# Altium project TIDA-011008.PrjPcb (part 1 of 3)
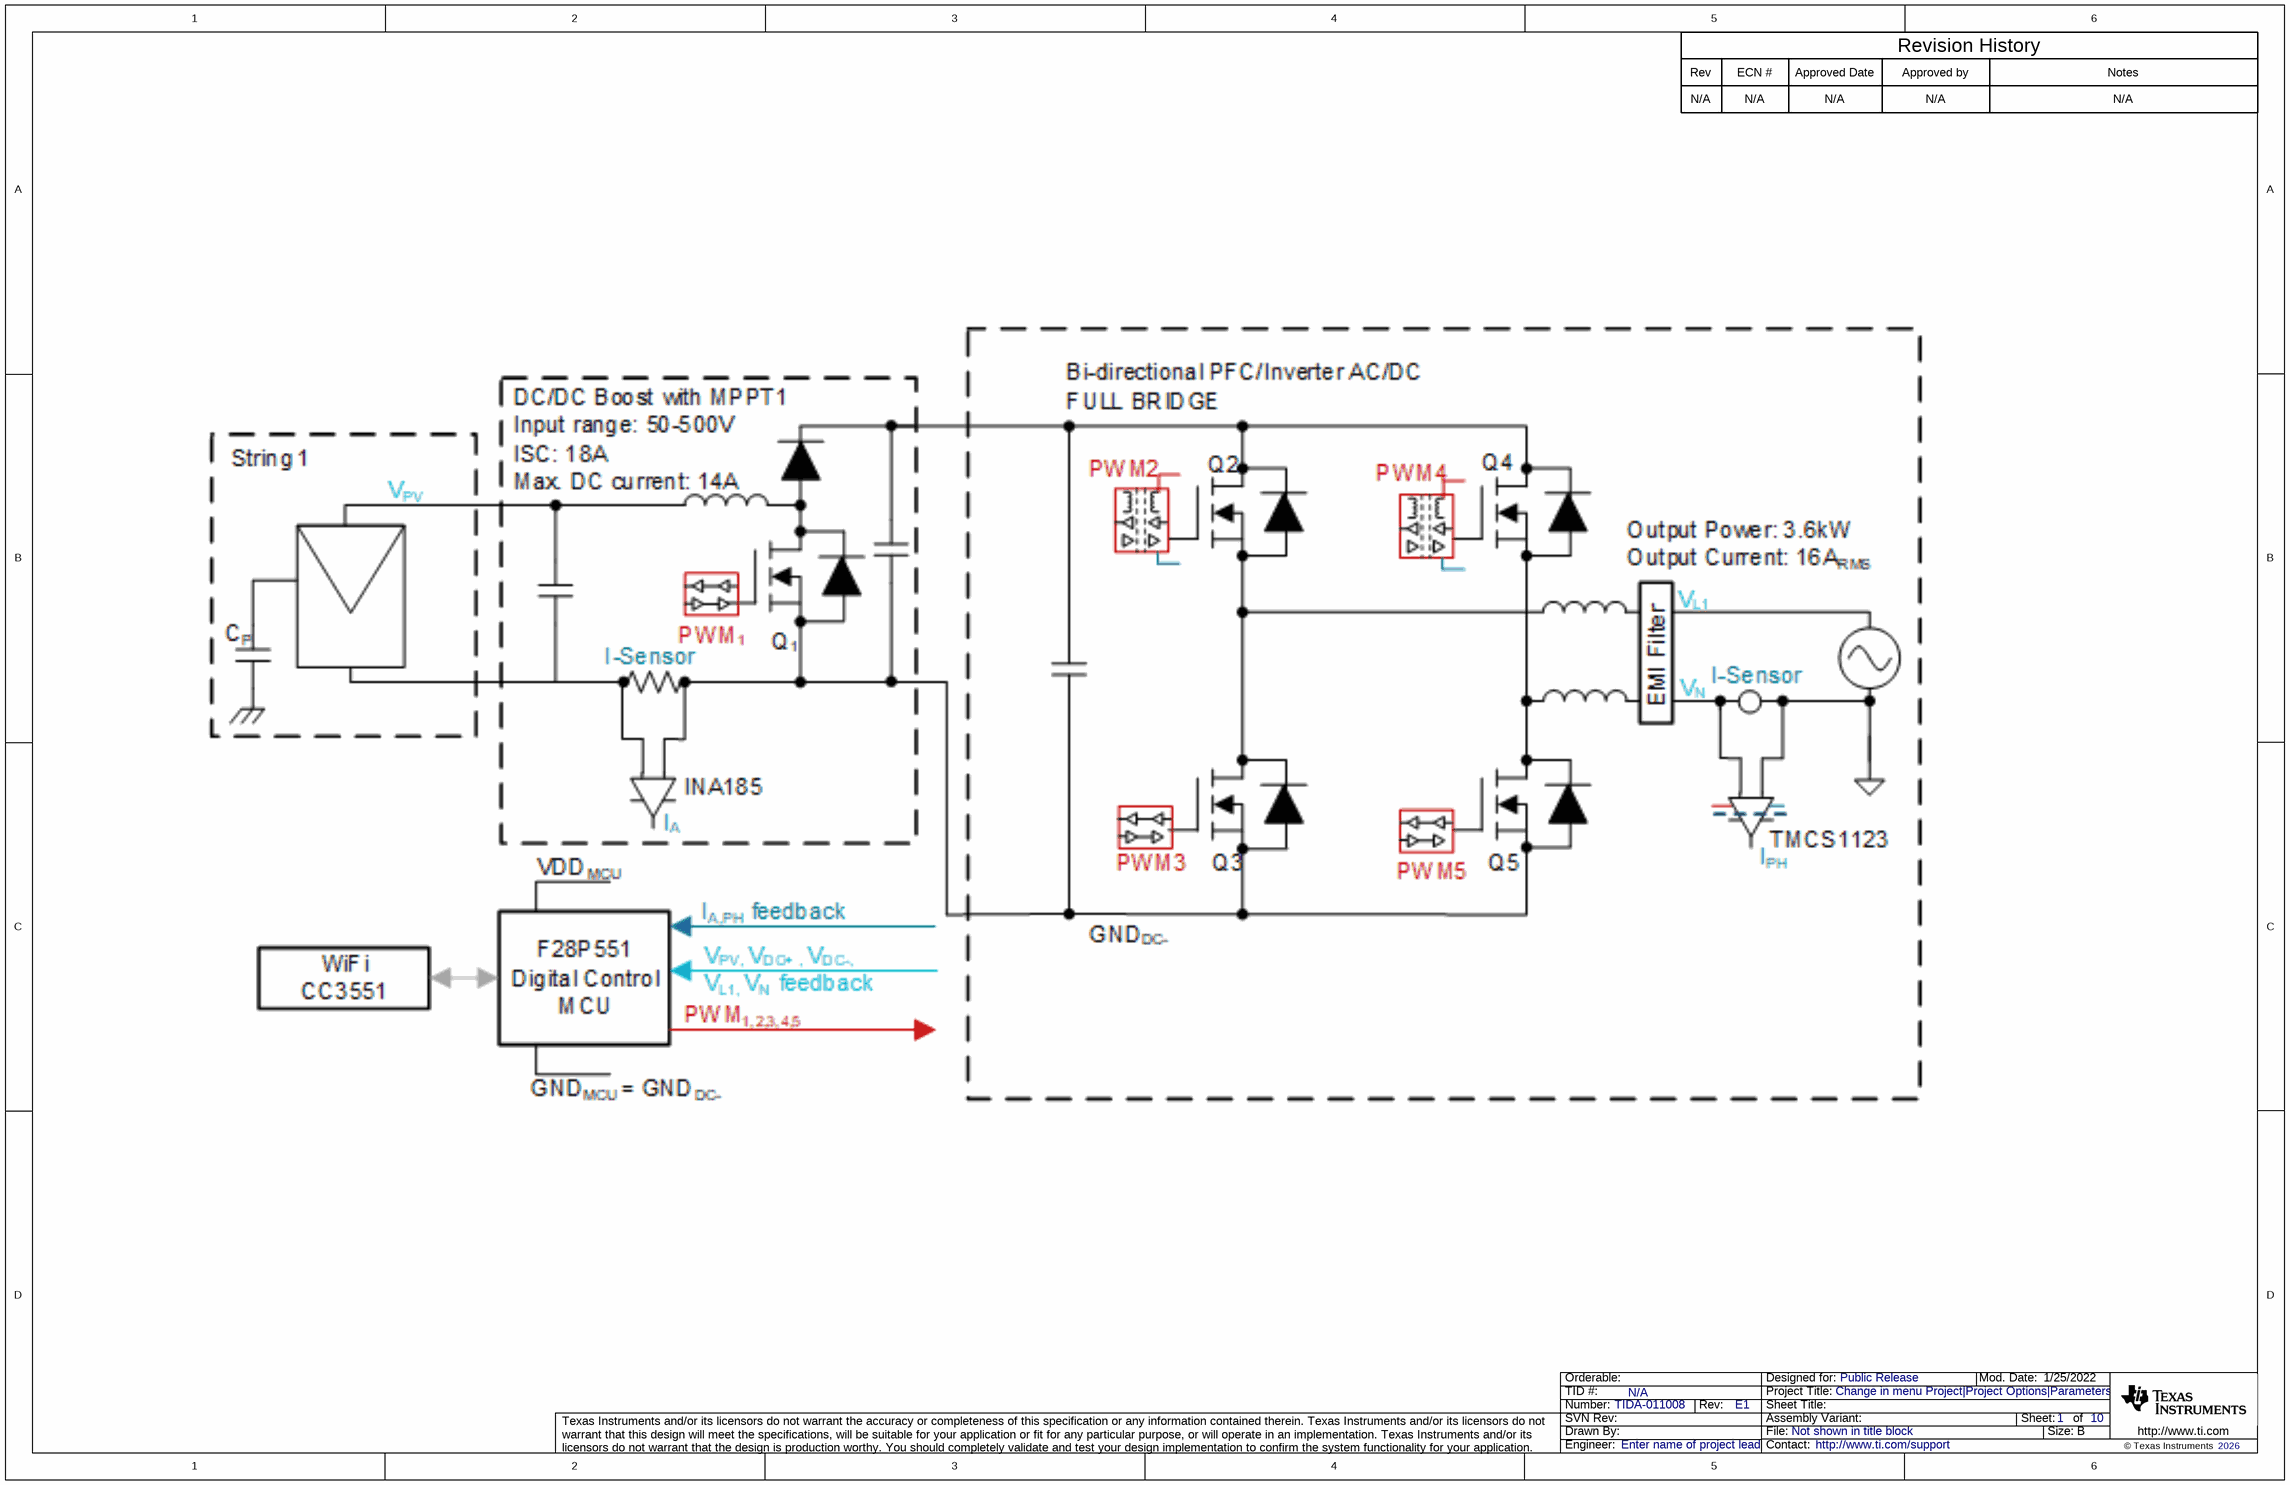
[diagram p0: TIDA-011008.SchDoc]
CopyrightYear: 2026; PCB_Layout: Who did the Layout?; PCB_Rev: E1; PRJ_Customer: Public Release; PRJ_Engineer: Enter name of project lead; PRJ_Number: TIDA-011008; PRJ_Title: Change in menu Project|Project Options|Parameters; SCH_Rev: E1; TechSupport: http://www.ti.com/support; TID: N/A
10 sheets, 518 parts. Net scope: hierarchical (ports join the sheet entries above them; power ports are global).
Board file: TIDA-011008.PcbDoc
Sheets:
  TIDA-011008.SchDoc
  TIDA-011008_CoverSheet.SchDoc
    U_TIDA-011008_Boost = TIDA-011008_Boost.SchDoc
    U_TIDA-011008_ACDC_EMI Filter = TIDA-011008_ACDC_EMI Filter.SchDoc
    U_TIDA-011008_Aux Power = TIDA-011008_Aux Power.SchDoc
    U_TIDA-011008_Control Stage = TIDA-011008_Control Stage.SchDoc
      U_TIDA-011008_WiFi Module = TIDA-011008_WiFi Module.SchDoc
    U_TIDA-011008_ACDC_Leg1 = TIDA-011008_ACDC_Leg.SchDoc
    U_TIDA-011008_ACDC_Leg2 = TIDA-011008_ACDC_Leg.SchDoc
    U_TIDA-011008_Measurements & AD Buffer = TIDA-011008_Measurements & AD Buffer.SchDoc
    U_TIDA-011008_Hardware = TIDA-011008_Hardware.SchDoc

## Sheet TIDA-011008.SchDoc
size 431 x 279 mm; Date: Not shown in title block; ApprovedBy: Not shown in title block; CheckedBy: Not shown in title block; Author: Not shown in title block; CompanyName: Not shown in title block; Engineer: Not shown in title block; Organization: Not shown in title block; Address1: Not shown in title block; Address2: Not shown in title block; Address3: Not shown in title block; Address4: Not shown in title block; DocumentNumber: 1; Revision: Use project parameter SCH_Rev; SheetNumber: 1; SheetTotal: 10; PageSetup: Record=PageOptions¦CenterHorizontal=True¦CenterVertical=True¦PrintScale=1.00¦XCorrection=1.00¦YCorrection=1.00¦PrintKind=0¦BorderSize=5000000¦LeftOffset=0¦BottomOffset=0¦Orientation=2¦PaperLength=1000¦PaperWidth=1000¦Scale=100¦PaperSource=15¦PrintQuality=600¦MediaType=1¦DitherType=10¦PaperKind=Letter¦PrintScaleMode=1

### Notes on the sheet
- Rev
- N/A
- ECN #
- Approved Date
- Approved by
- Revision History
- Notes

## Sheet TIDA-011008_CoverSheet.SchDoc
size 431 x 279 mm; Date: Not shown in title block; ApprovedBy: Not shown in title block; CheckedBy: Not shown in title block; Author: Not shown in title block; CompanyName: Not shown in title block; Engineer: Not shown in title block; Organization: Not shown in title block; Address1: Not shown in title block; Address2: Not shown in title block; Address3: Not shown in title block; Address4: Not shown in title block; DocumentNumber: 2; Revision: Use project parameter SCH_Rev; SheetNumber: 2; SheetTotal: 10; PageSetup: Record=PageOptions¦CenterHorizontal=True¦CenterVertical=True¦PrintScale=1.00¦XCorrection=1.00¦YCorrection=1.00¦PrintKind=0¦BorderSize=5000000¦LeftOffset=0¦BottomOffset=0¦Orientation=2¦PaperLength=1000¦PaperWidth=1000¦Scale=100¦PaperSource=15¦PrintQuality=600¦MediaType=1¦DitherType=10¦PaperKind=Letter¦PrintScaleMode=1
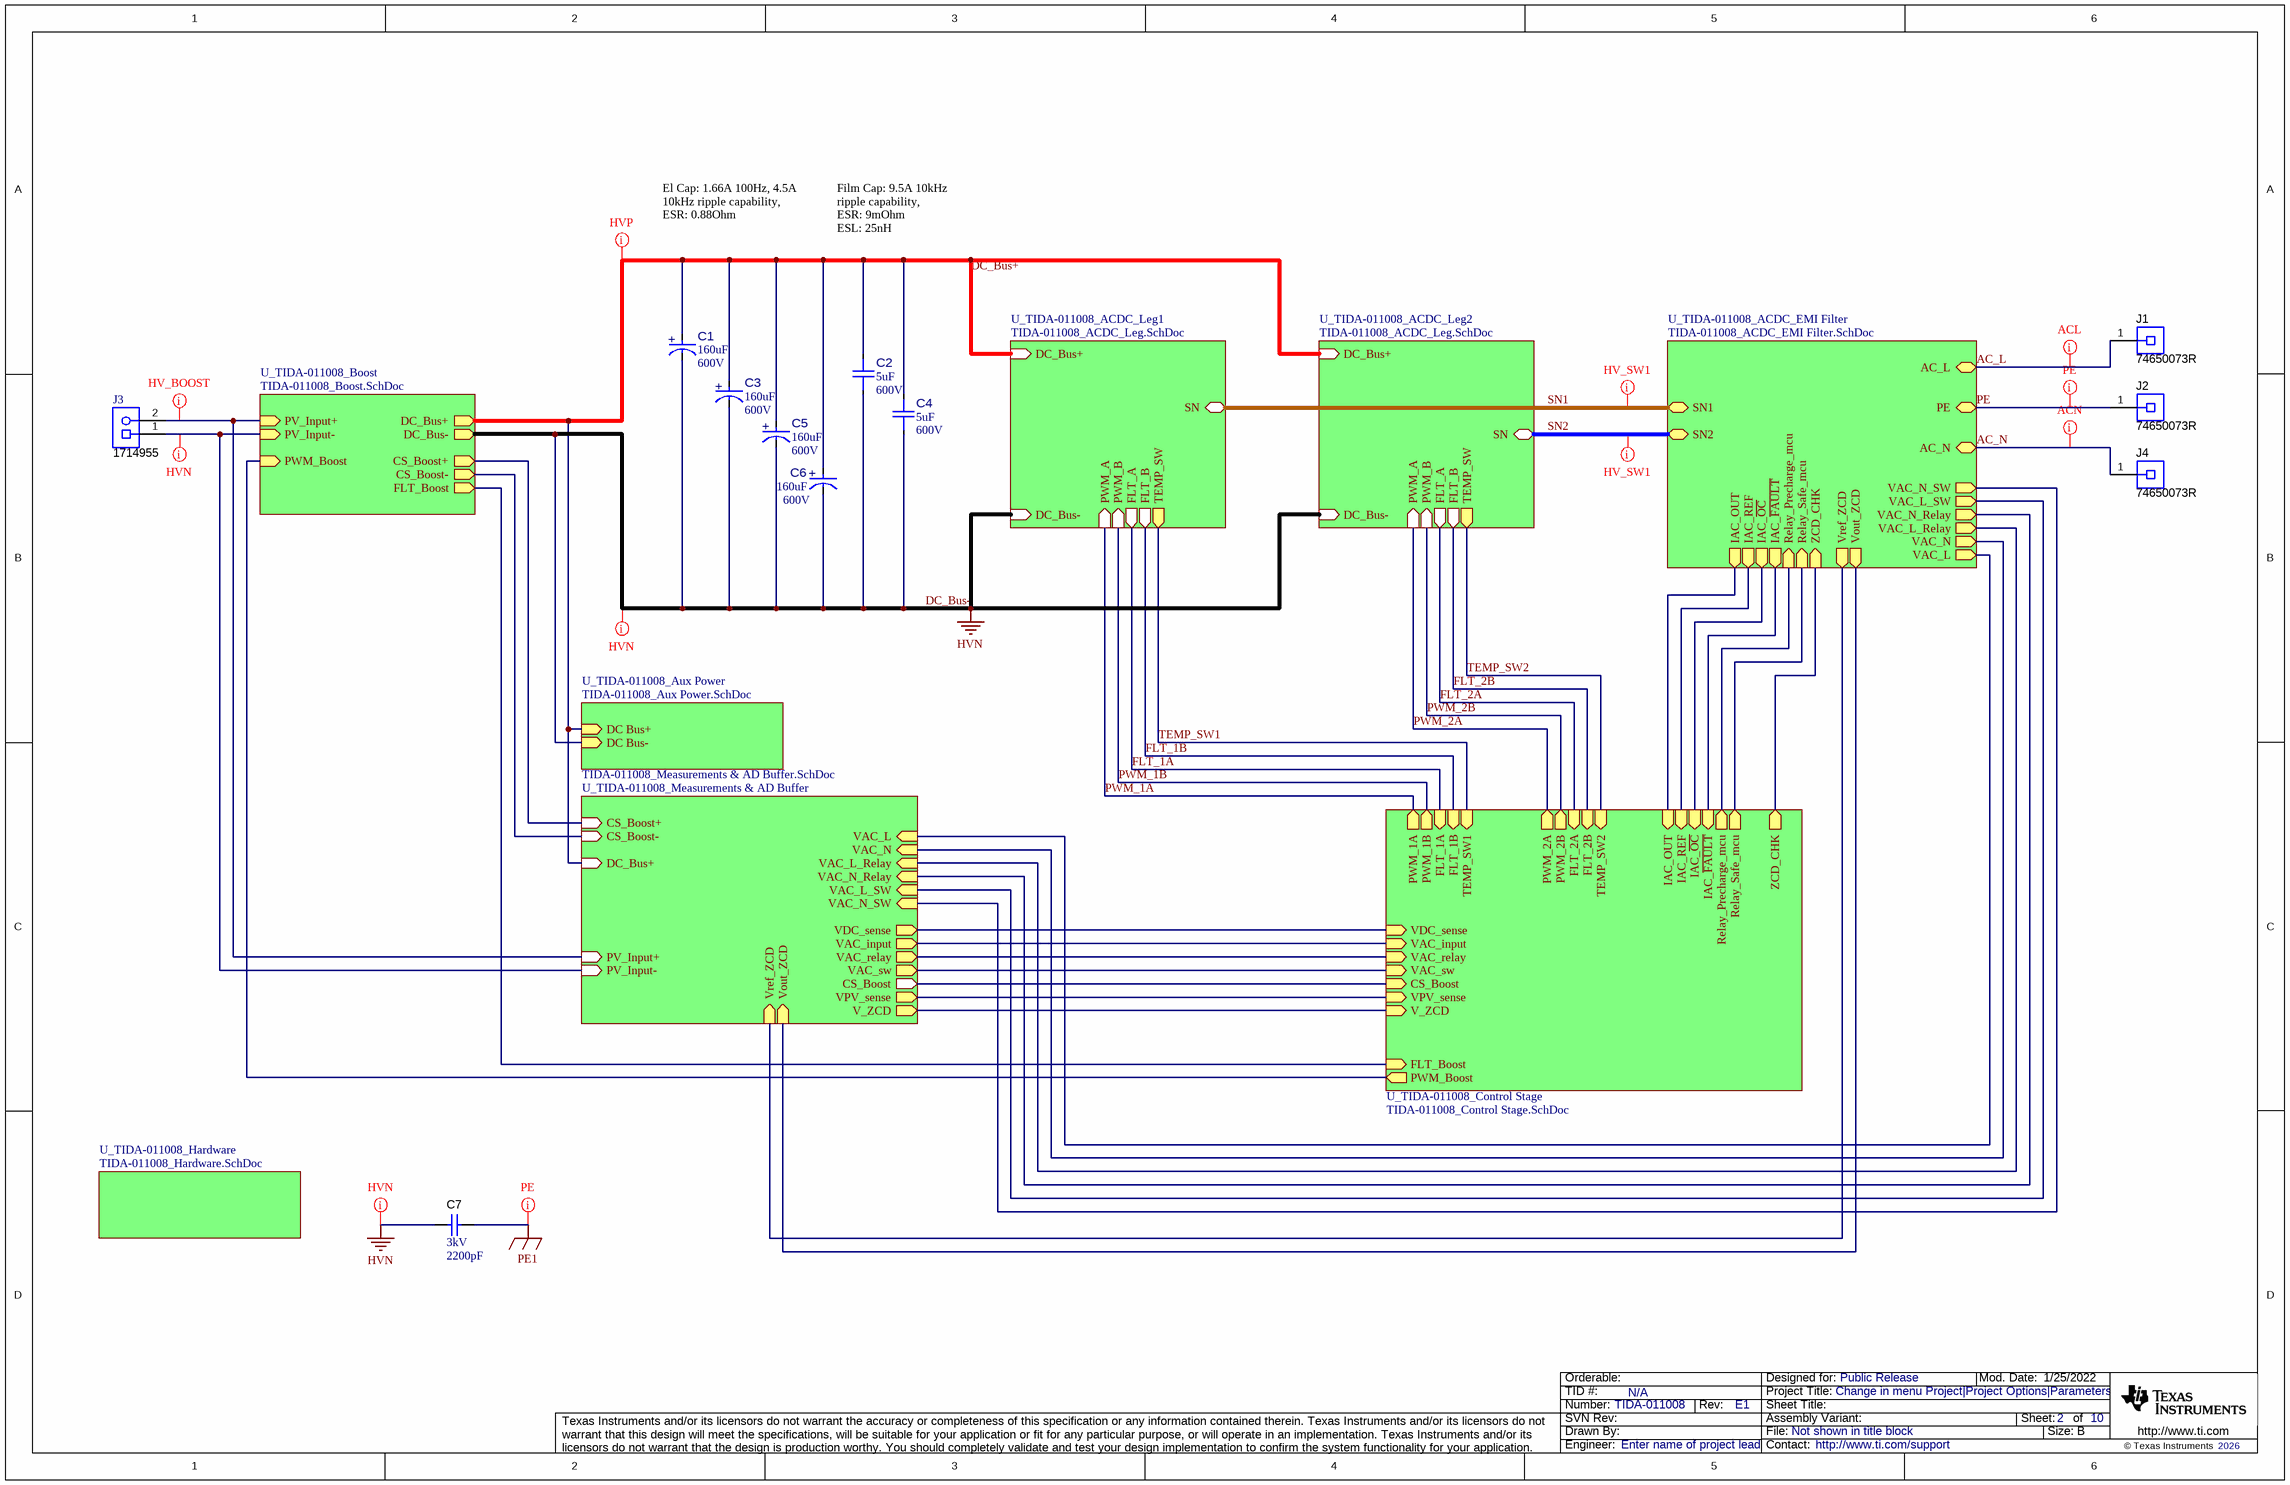
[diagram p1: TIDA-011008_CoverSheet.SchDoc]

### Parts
C1  ValueDisplayed: 160uF  VDC_V: 600V  [FP-ALH82D161DD600_RADIAL-MFG]  (hidden comment: ALH82D161DD600)
C2  ValueDisplayed: 5uF  VDC_V: 600V  [FP-FCS2SDS505K050IC90B_RADIAL-MFG]  (hidden comment: FCS2SDS505K050IC90B)
C3  ValueDisplayed: 160uF  VDC_V: 600V  [FP-ALH82D161DD600_RADIAL-MFG]  (hidden comment: ALH82D161DD600)
C4  ValueDisplayed: 5uF  VDC_V: 600V  [FP-FCS2SDS505K050IC90B_RADIAL-MFG]  (hidden comment: FCS2SDS505K050IC90B)
C5  ValueDisplayed: 160uF  VDC_V: 600V  [FP-ALH82D161DD600_RADIAL-MFG]  (hidden comment: ALH82D161DD600)
C6  ValueDisplayed: 160uF  VDC_V: 600V  [FP-ALH82D161DD600_RADIAL-MFG]  (hidden comment: ALH82D161DD600)
C7  VDC_V: 3kV  ValueDisplayed: 2200pF  [CK45_1250x600x1650]  (hidden comment: CK45-B3FD222KYVNA)
J1  74650073R  [Wurth_WP-THRBU]
J2  74650073R  [Wurth_WP-THRBU]
J3  1714955  [Phoenix_1714955]
J4  74650073R  [Wurth_WP-THRBU]

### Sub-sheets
U_TIDA-011008_ACDC_EMI Filter = TIDA-011008_ACDC_EMI Filter.SchDoc: IAC_OUT (out), IAC_~{OC} (out), IAC_~{FAULT} (out), IAC_REF (out), SN1 (bidir), SN2 (bidir), AC_L (bidir), AC_N (bidir), PE (bidir), Relay_Precharge_mcu (in), Relay_Safe_mcu (in), VAC_L_SW (out), VAC_N_SW (out), VAC_L_Relay (out), VAC_N_Relay (out), VAC_L (out), VAC_N (out), Vref_ZCD (out), Vout_ZCD (out), ZCD_CHK (in)
U_TIDA-011008_ACDC_Leg1 = TIDA-011008_ACDC_Leg.SchDoc: SN (bidir), PWM_A (in), FLT_A (out), PWM_B (in), DC_Bus+ (in), DC_Bus- (in), FLT_B (out), TEMP_SW (out)
U_TIDA-011008_ACDC_Leg2 = TIDA-011008_ACDC_Leg.SchDoc: SN (bidir), PWM_A (in), FLT_A (out), PWM_B (in), DC_Bus+ (in), DC_Bus- (in), FLT_B (out), TEMP_SW (out)
U_TIDA-011008_Aux Power = TIDA-011008_Aux Power.SchDoc: DC Bus+ (in), DC Bus- (in)
U_TIDA-011008_Boost = TIDA-011008_Boost.SchDoc: CS_Boost+ (out), CS_Boost- (out), PWM_Boost (in), DC_Bus+ (out), DC_Bus- (out), PV_Input+ (in), PV_Input- (in), FLT_Boost (out)
U_TIDA-011008_Control Stage = TIDA-011008_Control Stage.SchDoc: FLT_Boost (in), PWM_Boost (out), FLT_1B (in), FLT_2B (in), FLT_1A (in), FLT_2A (in), PWM_1A (out), PWM_1B (out), PWM_2A (out), PWM_2B (out), VDC_sense (in), VAC_input (in), VAC_relay (in), VAC_sw (in), CS_Boost (in), VPV_sense (in), IAC_OUT (in), IAC_REF (in), TEMP_SW2 (in), TEMP_SW1 (in), IAC_~{OC} (in), IAC_~{FAULT} (in), Relay_Precharge_mcu (out), Relay_Safe_mcu (out), V_ZCD (in), ZCD_CHK (out)
U_TIDA-011008_Hardware = TIDA-011008_Hardware.SchDoc: no entries
U_TIDA-011008_Measurements & AD Buffer = TIDA-011008_Measurements & AD Buffer.SchDoc: PV_Input+ (in), PV_Input- (in), DC_Bus+ (in), VAC_L (in), VAC_N (in), VAC_L_Relay (in), VAC_N_Relay (in), VAC_L_SW (in), VAC_N_SW (in), VAC_input (out), CS_Boost (out), CS_Boost+ (in), CS_Boost- (in), VAC_relay (out), VAC_sw (out), VDC_sense (out), VPV_sense (out), Vref_ZCD (in), Vout_ZCD (in), V_ZCD (out)

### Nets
DC_Bus-: C1.1(CATHODE) C2.1 C3.1(CATHODE) C4.1 C5.1(CATHODE) C6.1(CATHODE) C7.2 ; sheet U_TIDA-011008_Boost/DC_Bus-, sheet U_TIDA-011008_Aux Power/DC Bus-, sheet U_TIDA-011008_ACDC_Leg1/DC_Bus-, sheet U_TIDA-011008_ACDC_Leg2/DC_Bus-  [also labelled HVN]
PE: J2.1 ; sheet U_TIDA-011008_ACDC_EMI Filter/PE
PE1: C7.1
AC_L: J1.1 ; sheet U_TIDA-011008_ACDC_EMI Filter/AC_L
AC_N: J4.1 ; sheet U_TIDA-011008_ACDC_EMI Filter/AC_N
CS_Boost: sheet U_TIDA-011008_Control Stage/CS_Boost, sheet U_TIDA-011008_Measurements & AD Buffer/CS_Boost
CS_Boost+: sheet U_TIDA-011008_Boost/CS_Boost+, sheet U_TIDA-011008_Measurements & AD Buffer/CS_Boost+
CS_Boost-: sheet U_TIDA-011008_Boost/CS_Boost-, sheet U_TIDA-011008_Measurements & AD Buffer/CS_Boost-
DC_Bus+: C1.2(ANODE) C2.2 C3.2(ANODE) C4.2 C5.2(ANODE) C6.2(ANODE) ; sheet U_TIDA-011008_Boost/DC_Bus+, sheet U_TIDA-011008_Aux Power/DC Bus+, sheet U_TIDA-011008_ACDC_Leg1/DC_Bus+, sheet U_TIDA-011008_ACDC_Leg2/DC_Bus+, sheet U_TIDA-011008_Measurements & AD Buffer/DC_Bus+
FLT_1A: sheet U_TIDA-011008_Control Stage/FLT_1A, sheet U_TIDA-011008_ACDC_Leg1/FLT_A
FLT_1B: sheet U_TIDA-011008_Control Stage/FLT_1B, sheet U_TIDA-011008_ACDC_Leg1/FLT_B
FLT_2A: sheet U_TIDA-011008_Control Stage/FLT_2A, sheet U_TIDA-011008_ACDC_Leg2/FLT_A
FLT_2B: sheet U_TIDA-011008_Control Stage/FLT_2B, sheet U_TIDA-011008_ACDC_Leg2/FLT_B
FLT_Boost: sheet U_TIDA-011008_Boost/FLT_Boost, sheet U_TIDA-011008_Control Stage/FLT_Boost
IAC_~{FAULT}: sheet U_TIDA-011008_ACDC_EMI Filter/IAC_~{FAULT}, sheet U_TIDA-011008_Control Stage/IAC_~{FAULT}
IAC_~{OC}: sheet U_TIDA-011008_ACDC_EMI Filter/IAC_~{OC}, sheet U_TIDA-011008_Control Stage/IAC_~{OC}
IAC_OUT: sheet U_TIDA-011008_ACDC_EMI Filter/IAC_OUT, sheet U_TIDA-011008_Control Stage/IAC_OUT
IAC_REF: sheet U_TIDA-011008_ACDC_EMI Filter/IAC_REF, sheet U_TIDA-011008_Control Stage/IAC_REF
PV_Input+: J3.2 ; sheet U_TIDA-011008_Boost/PV_Input+, sheet U_TIDA-011008_Measurements & AD Buffer/PV_Input+
PV_Input-: J3.1 ; sheet U_TIDA-011008_Boost/PV_Input-, sheet U_TIDA-011008_Measurements & AD Buffer/PV_Input-
PWM_1A: sheet U_TIDA-011008_Control Stage/PWM_1A, sheet U_TIDA-011008_ACDC_Leg1/PWM_A
PWM_1B: sheet U_TIDA-011008_Control Stage/PWM_1B, sheet U_TIDA-011008_ACDC_Leg1/PWM_B
PWM_2A: sheet U_TIDA-011008_Control Stage/PWM_2A, sheet U_TIDA-011008_ACDC_Leg2/PWM_A
PWM_2B: sheet U_TIDA-011008_Control Stage/PWM_2B, sheet U_TIDA-011008_ACDC_Leg2/PWM_B
PWM_Boost: sheet U_TIDA-011008_Boost/PWM_Boost, sheet U_TIDA-011008_Control Stage/PWM_Boost
Relay_Precharge_mcu: sheet U_TIDA-011008_ACDC_EMI Filter/Relay_Precharge_mcu, sheet U_TIDA-011008_Control Stage/Relay_Precharge_mcu
Relay_Safe_mcu: sheet U_TIDA-011008_ACDC_EMI Filter/Relay_Safe_mcu, sheet U_TIDA-011008_Control Stage/Relay_Safe_mcu
SN1: sheet U_TIDA-011008_ACDC_EMI Filter/SN1, sheet U_TIDA-011008_ACDC_Leg1/SN
SN2: sheet U_TIDA-011008_ACDC_EMI Filter/SN2, sheet U_TIDA-011008_ACDC_Leg2/SN
TEMP_SW1: sheet U_TIDA-011008_Control Stage/TEMP_SW1, sheet U_TIDA-011008_ACDC_Leg1/TEMP_SW
TEMP_SW2: sheet U_TIDA-011008_Control Stage/TEMP_SW2, sheet U_TIDA-011008_ACDC_Leg2/TEMP_SW
V_ZCD: sheet U_TIDA-011008_Control Stage/V_ZCD, sheet U_TIDA-011008_Measurements & AD Buffer/V_ZCD
VAC_input: sheet U_TIDA-011008_Control Stage/VAC_input, sheet U_TIDA-011008_Measurements & AD Buffer/VAC_input
VAC_L: sheet U_TIDA-011008_ACDC_EMI Filter/VAC_L, sheet U_TIDA-011008_Measurements & AD Buffer/VAC_L
VAC_L_Relay: sheet U_TIDA-011008_ACDC_EMI Filter/VAC_L_Relay, sheet U_TIDA-011008_Measurements & AD Buffer/VAC_L_Relay
VAC_L_SW: sheet U_TIDA-011008_ACDC_EMI Filter/VAC_L_SW, sheet U_TIDA-011008_Measurements & AD Buffer/VAC_L_SW
VAC_N: sheet U_TIDA-011008_ACDC_EMI Filter/VAC_N, sheet U_TIDA-011008_Measurements & AD Buffer/VAC_N
VAC_N_Relay: sheet U_TIDA-011008_ACDC_EMI Filter/VAC_N_Relay, sheet U_TIDA-011008_Measurements & AD Buffer/VAC_N_Relay
VAC_N_SW: sheet U_TIDA-011008_ACDC_EMI Filter/VAC_N_SW, sheet U_TIDA-011008_Measurements & AD Buffer/VAC_N_SW
VAC_relay: sheet U_TIDA-011008_Control Stage/VAC_relay, sheet U_TIDA-011008_Measurements & AD Buffer/VAC_relay
VAC_sw: sheet U_TIDA-011008_Control Stage/VAC_sw, sheet U_TIDA-011008_Measurements & AD Buffer/VAC_sw
VDC_sense: sheet U_TIDA-011008_Control Stage/VDC_sense, sheet U_TIDA-011008_Measurements & AD Buffer/VDC_sense
Vout_ZCD: sheet U_TIDA-011008_ACDC_EMI Filter/Vout_ZCD, sheet U_TIDA-011008_Measurements & AD Buffer/Vout_ZCD
VPV_sense: sheet U_TIDA-011008_Control Stage/VPV_sense, sheet U_TIDA-011008_Measurements & AD Buffer/VPV_sense
Vref_ZCD: sheet U_TIDA-011008_ACDC_EMI Filter/Vref_ZCD, sheet U_TIDA-011008_Measurements & AD Buffer/Vref_ZCD
ZCD_CHK: sheet U_TIDA-011008_ACDC_EMI Filter/ZCD_CHK, sheet U_TIDA-011008_Control Stage/ZCD_CHK

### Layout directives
net class HVP: DC_Bus+
net class HVN: DC_Bus-, PV_Input-
net class HV_SW1: SN1, SN2
net class ACL: AC_L
net class PE: PE, PE1
net class ACN: AC_N
net class HV_BOOST: PV_Input+

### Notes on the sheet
- El Cap: 1.66A 100Hz, 4.5A 10kHz ripple capability,
  ESR: 0.88Ohm
- Film Cap: 9.5A 10kHz ripple capability,
  ESR: 9mOhm
  ESL: 25nH

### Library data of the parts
C1 C3 C5 C6 = CMP-0033686-1: ALH82, Aluminum Electrolytic, 160 uF, 20%, 600 VDC, -40/+105°C; Manufacturer: KEMET; AEC Qualified: No; Cap_F: 160µF; IRMS_A: 4.51A; SizeZ_mm: 42mm; Esr: 0.877; Leakage Current: 288uA; Life: 3000Hours; Value: 160µF
C2 C4 = CMP-0128404-1: Film Capacitor 5uF 10% 600V 32x14x28mm TH; Manufacturer: Jianghai; AEC Qualified: No; Cap_F: 5µF; SizeZ_mm: 28mm; Value: 5µF
C7 = CMP-0086078-1: CAP, CERM, 2200 pF, 3000 V,+/- 10%, B, Dia 12.5mm; Manufacturer: TDK; AEC Qualified: N; SizeAreaWB_mm2: 116; Cap_Case: 12.5x6x16.5mm; SizeZ_mm: 16.5; AEC Category: Q200; TaMin_C: -25°C; SizeX_mm: 12.5; SizeY_mm: 6; Value2: 3000V; TaMax_C: 105°C; Value: 2200pF; SizeArea_mm2: 75; U/M: EA; Cap_F: 2.2nF
J1 J2 J4 = CMP-0078526-1: Power Element Bush, M3, TH; Manufacturer: Wurth Elektronik; Gender: Female; Current_A: 50A; ContactFinish: Tin; CompType: Screw Terminal
J3 = CMP-0055505-1: Terminal Block, 2x1, 6.35mm, Green, TH; Manufacturer: Phoenix Contact; CNHeader: FALSE; Shrouded: Y; Gender: Female; Row_Count: 1; Pitch_mm: 6.35; CT: TRUE

## Sheet TIDA-011008_Boost.SchDoc
size 431 x 279 mm; Date: Not shown in title block; ApprovedBy: Not shown in title block; CheckedBy: Not shown in title block; Author: Not shown in title block; CompanyName: Not shown in title block; Engineer: Not shown in title block; Organization: Not shown in title block; Address1: Not shown in title block; Address2: Not shown in title block; Address3: Not shown in title block; Address4: Not shown in title block; DocumentNumber: 1; Revision: Use project parameter SCH_Rev; SheetNumber: 4; SheetTotal: 10; PageSetup: Record=PageOptions¦CenterHorizontal=True¦CenterVertical=True¦PrintScale=1.00¦XCorrection=1.00¦YCorrection=1.00¦PrintKind=0¦BorderSize=5000000¦LeftOffset=0¦BottomOffset=0¦Orientation=2¦PaperLength=1000¦PaperWidth=1000¦Scale=100¦PaperSource=15¦PrintQuality=600¦MediaType=1¦DitherType=10¦PaperKind=Letter¦PrintScaleMode=1
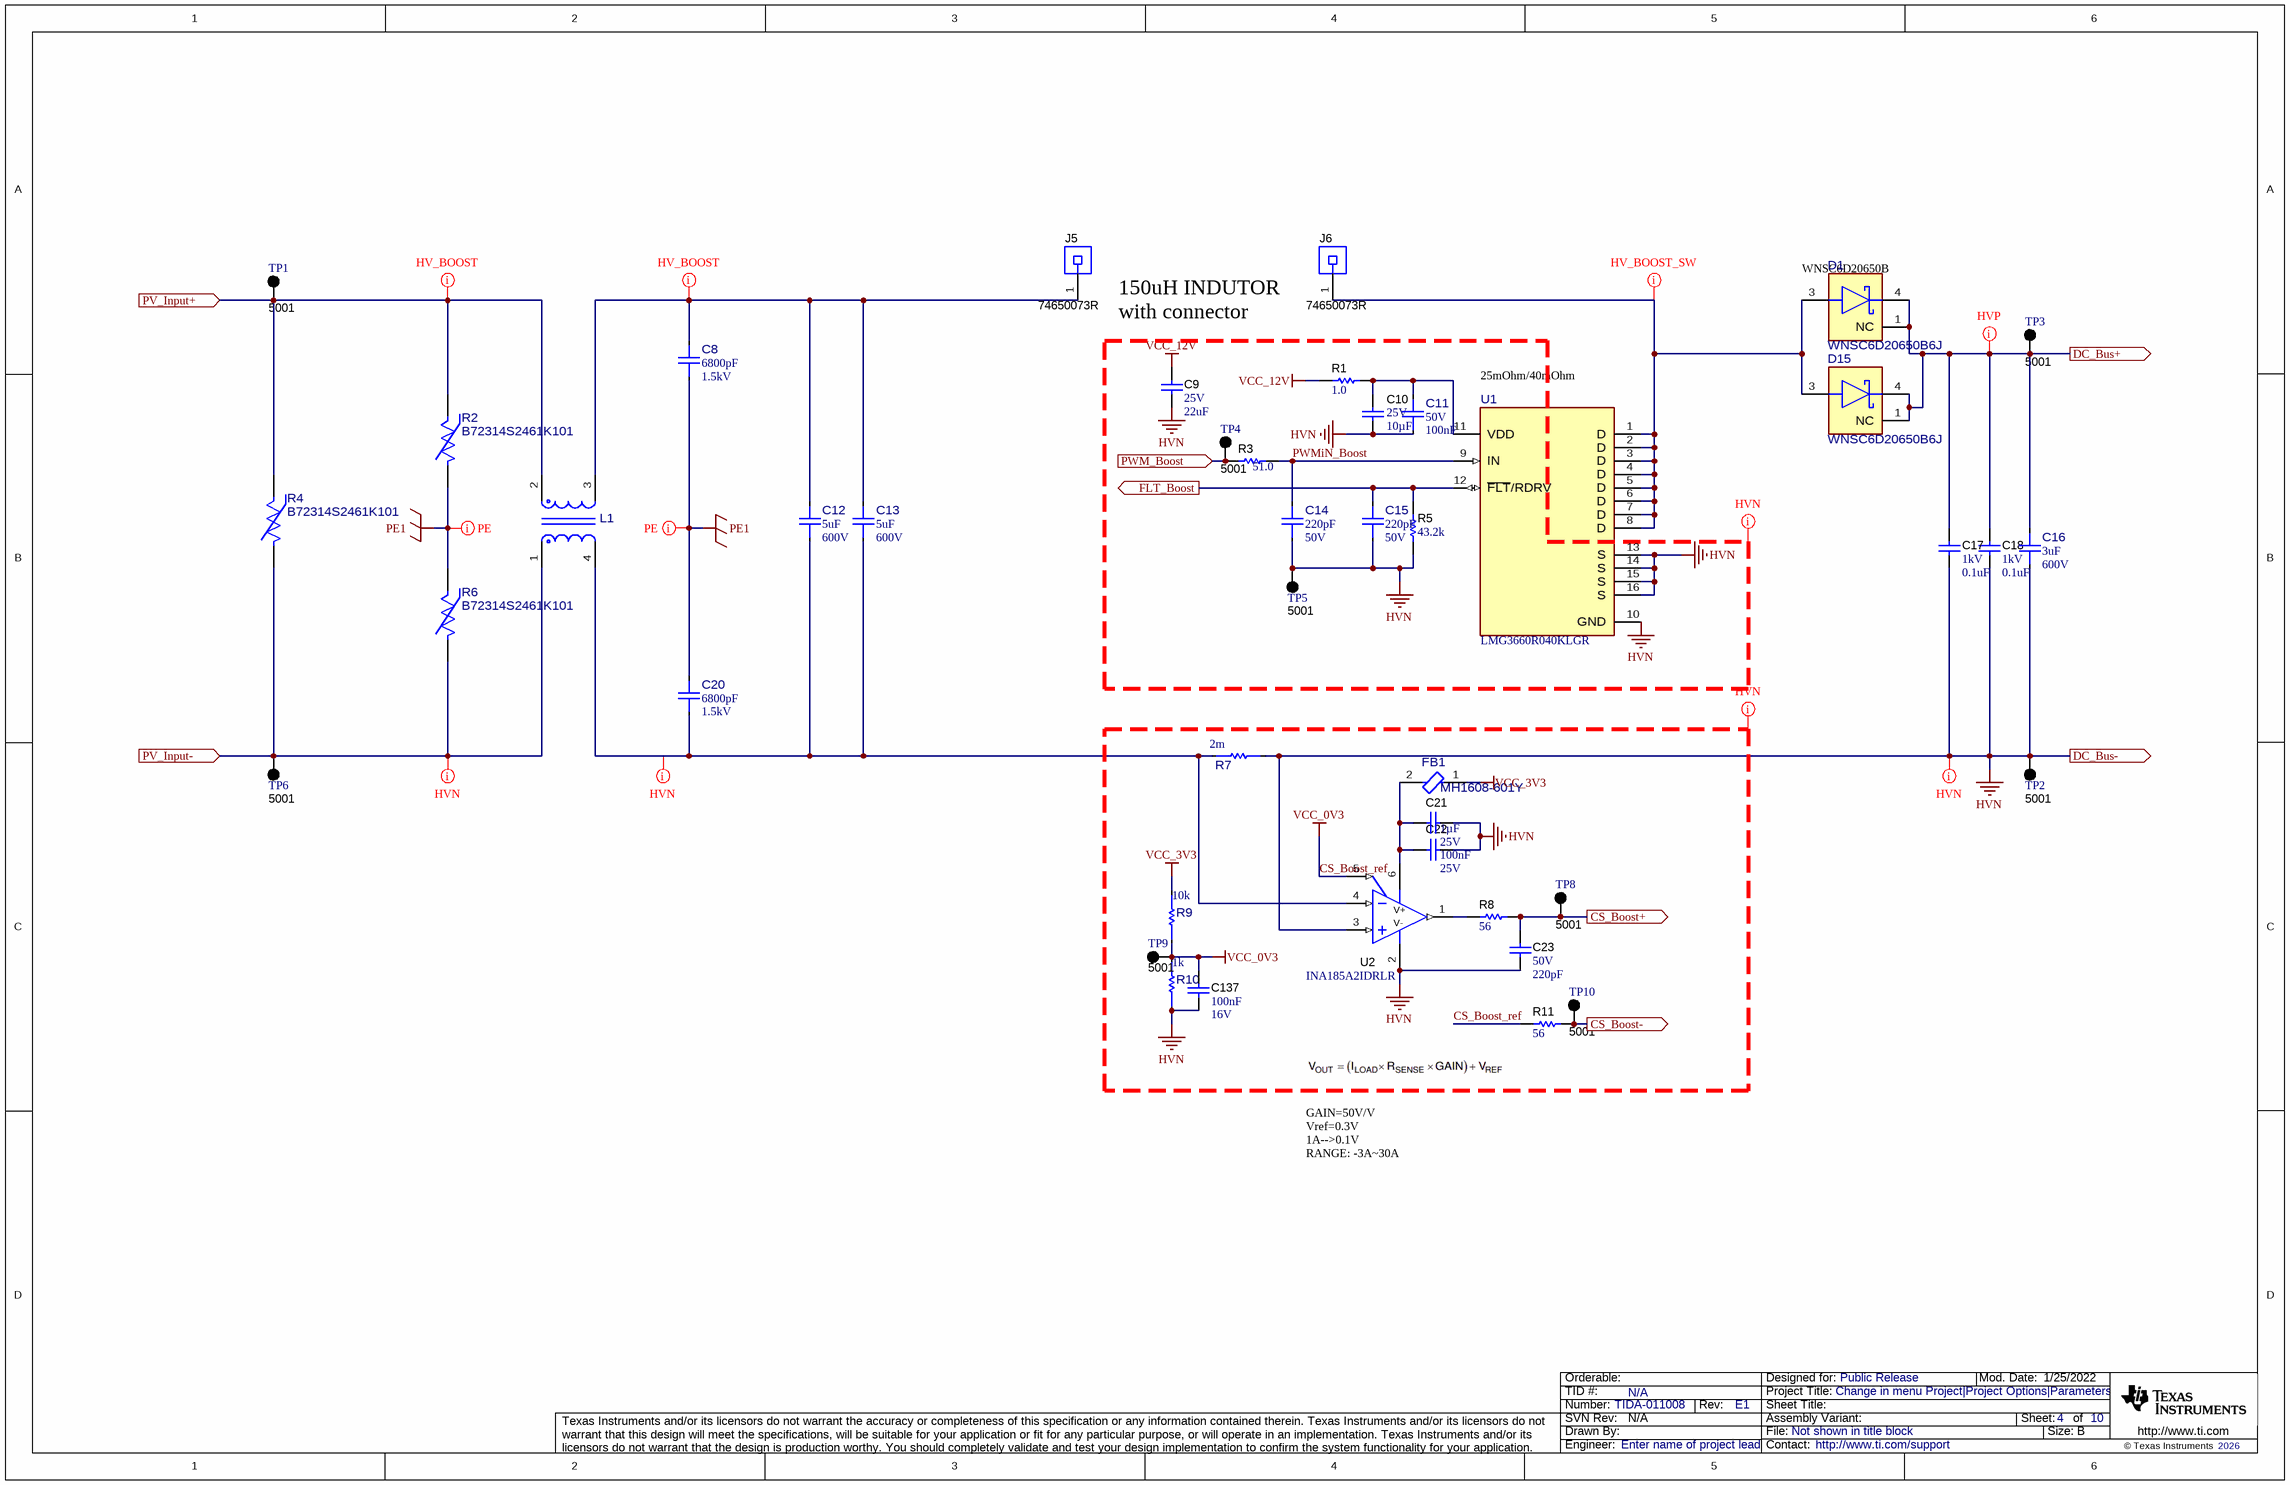
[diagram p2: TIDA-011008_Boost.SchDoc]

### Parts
C8  ValueDisplayed: 6800pF  VDC_V: 1.5kV  [FP-R413F168050T0K_RADIAL-MFG]  (hidden comment: R413F168050T0K)
C9  VDC_V: 25V  ValueDisplayed: 22uF  [1210_280]  (hidden comment: 12103D226MAT2A)
C10  VDC_V: 25V  ValueDisplayed: 10µF  [1206_180]  (hidden comment: TMK316AB7106KLHT)
C11  VDC_V: 50V  Cap_F: 100nF  [FP-GCM188R71H104KA57J_0603-MFG]  (hidden comment: GCM188R71H104KA57J)
C12  ValueDisplayed: 5uF  VDC_V: 600V  [FP-FCS2SDS505K050IC90B_RADIAL-MFG]  (hidden comment: FCS2SDS505K050IC90B)
C13  ValueDisplayed: 5uF  VDC_V: 600V  [FP-FCS2SDS505K050IC90B_RADIAL-MFG]  (hidden comment: FCS2SDS505K050IC90B)
C14  ValueDisplayed: 220pF  VDC_V: 50V  [FP-C0603C221J5GAC7867_0603-MFG]  (hidden comment: C0603C221J5GAC7867)
C15  ValueDisplayed: 220pF  VDC_V: 50V  [FP-C0603C221J5GAC7867_0603-MFG]  (hidden comment: C0603C221J5GAC7867)
C16  ValueDisplayed: 3uF  VDC_V: 600V  [FP-FCS2SDS305K050I490B_RADIAL-MFG]  (hidden comment: FCS2SDS305K050I490B)
C17  VDC_V: 1kV  ValueDisplayed: 0.1uF  [1812_254]  (hidden comment: C1812V104KDRACTU)
C18  VDC_V: 1kV  ValueDisplayed: 0.1uF  [1812_254]  (hidden comment: C1812V104KDRACTU)
C20  ValueDisplayed: 6800pF  VDC_V: 1.5kV  [FP-R413F168050T0K_RADIAL-MFG]  (hidden comment: R413F168050T0K)
C21  VDC_V: 25V  ValueDisplayed: 1µF  [0603]  (hidden comment: TMK107BJ105KA-T)
C22  Cap_F: 100nF  VDC_V: 25V  [0603]  (hidden comment: 06033C104JAT2A)
C23  VDC_V: 50V  ValueDisplayed: 220pF  [0603]  (hidden comment: GRM1885C1H221JA01D)
C137  Cap_F: 100nF  VDC_V: 16V  [0603]  (hidden comment: GRM188R71C104KA01D)
D1  WNSC6D20650B6J  [FP-WNSC6D20650B6J_TO263-MFG]
D15  WNSC6D20650B6J  [FP-WNSC6D20650B6J_TO263-MFG]
FB1  MH1608-601Y  [FP-MH1608-601Y_0603-MFG]
J5  74650073R  [Wurth_WP-THRBU]
J6  74650073R  [Wurth_WP-THRBU]
L1  YXA80182T-3  [FP-YXA80182T-3_pth4-MFG]  (value not drawn)
R1  ValueDisplayed: 1.0  [0603]  (hidden comment: CRCW06031R00JNEA)
R2  B72314S2461K101  [FP-B72314S2461K101_RADIAL-MFG]
R3  ValueDisplayed: 51.0  [0603]  (hidden comment: RC0603FR-0751RL)
R4  B72314S2461K101  [FP-B72314S2461K101_RADIAL-MFG]
R5  ValueDisplayed: 43.2k  [0603]  (hidden comment: RC0603FR-0743K2L)
R6  B72314S2461K101  [FP-B72314S2461K101_RADIAL-MFG]
R7  value 2m  [FP-CSS2H-2512K-2L00F_2512-MFG]  (hidden comment: CSS2H-2512K-2L00F)
R8  ValueDisplayed: 56  [0603]  (hidden comment: CRCW060356R0JNEA)
R9  value 10k  [FP-CRCW060310K0FKEAC_0603-MFG]  (hidden comment: CRCW060310K0FKEAC)
R10  value 1k  [FP-CRCW06031K00FKEAC_0603-MFG]  (hidden comment: CRCW06031K00FKEAC)
R11  ValueDisplayed: 56  [0603]  (hidden comment: CRCW060356R0JNEA)
TP1  5001  [Keystone5001]
TP2  5001  [Keystone5001]
TP3  5001  [Keystone5001]
TP4  5001  [Keystone5001]
TP5  5001  [Keystone5001]
TP6  5001  [Keystone5001]
TP8  5001  [Keystone5001]
TP9  5001  [Keystone5001]
TP10  5001  [Keystone5001]
U1  LMG3660R040KLGR  [KLG0016A-MFG]
U2  INA185A2IDRLR  [DRL0006A]

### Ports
CS_Boost+ (out), CS_Boost- (out), DC_Bus+ (out), DC_Bus- (out), FLT_Boost (out), PV_Input+ (in), PV_Input- (in), PWM_Boost (in)

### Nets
CS_Boost_ref: C137.1 R9.1 R10.2 R11.1 TP9.1 U2.5(REF)  [also labelled VCC_0V3]
HVN: C9.2 C10.2 C11.1 C14.1 C15.1 C16.1 C17.2 C18.2 C21.2 C22.2 C23.2 C137.2 R5.1 R7.2 R10.1 TP2.1 TP5.1 U1.10(GND) U1.13(S) U1.14(S) U1.15(S) U1.16(S) U2.2(V-) U2.3(IN+) ; port DC_Bus-  [project net DC_Bus-]
PE1: C8.1 C20.2 R2.1 R6.2
VCC_3V3: FB1.1 R9.2
VCC_12V: C9.1 R1.1
CS_Boost+: C23.1 R8.2 TP8.1 ; port CS_Boost+
CS_Boost-: R11.2 TP10.1 ; port CS_Boost-
DC_Bus+: C16.2 C17.1 C18.1 D1.1(NC) D1.4(K) D15.1(NC) D15.4(K) TP3.1 ; port DC_Bus+
FLT_Boost: C15.2 R5.2 U1.12(~{FLT}/RDRV) ; port FLT_Boost
PV_Input+: L1.2 R2.2 R4.2 TP1.1 ; port PV_Input+
PV_Input-: L1.1 R4.1 R6.1 TP6.1 ; port PV_Input-
PWM_Boost: R3.1 TP4.1 ; port PWM_Boost
PWMiN_Boost: C14.2 R3.2 U1.9(IN)
NetC8_2: C8.2 C12.2 C13.2 J5.1 L1.3
NetC10_1: C10.1 C11.2 R1.2 U1.11(VDD)
NetC12_1: C12.1 C13.1 C20.1 L1.4 R7.1 U2.4(IN-)
NetC21_1: C21.1 C22.1 FB1.2 U2.6(V+)
NetD1_3: D1.3(A) D15.3(A) J6.1 U1.1(D) U1.2(D) U1.3(D) U1.4(D) U1.5(D) U1.6(D) U1.7(D) U1.8(D)
NetR8_1: R8.1 U2.1(OUT)

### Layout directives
net class HV_BOOST: NetC8_2, PV_Input+
net class HV_BOOST_SW: NetD1_3
net class HVP: DC_Bus+
net class HVN: CS_Boost_ref, DC_Bus-, HVN, NetC12_1, PV_Input-, PWMiN_Boost, VCC_0V3, VCC_3V3, VCC_12V
net class PE: PE1

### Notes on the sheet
- 150uH INDUTOR with connector
- (near D1) WNSC6D20650B
- 25mOhm/40mOhm
- GAIN=50V/V
  Vref=0.3V
  1A-->0.1V
  RANGE: -3A~30A

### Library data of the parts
C8 C20 = CMP-0042924-1: 6800 pF Film Capacitor 300V 1500V (1.5kV) Polypropylene (PP), Metallized Radial; Manufacturer: KEMET; AEC Grade: Grade 1; AEC Qualified: Yes; Cap_F: 6.8nF; SizeZ_mm: 12.1mm; Tolerance_%: 10%; VAC_Y: Y2; Value: 6.8nF
C9 = CMP-0009063-2: CAP, CERM, 22 uF, 25 V, +/- 20%, X5R, 1210; Manufacturer: AVX; TaMin_C: -55°C; Polarized: N; SizeAreaWB_mm2: 14.7; Value1: Unknown; U/M: EA; Value: 22uF; TaMax_C: 85°C; SizeZ_mm: 2.8; SizeX_mm: 3.2; SizeY_mm: 2.5; Cap_Case: 1210; SizeArea_mm2: 8; Cap_F: 22µF; AEC Category: Q200
C10 = CMP-0750154-1: CAP, CERM, 10 µF, 25 V,+/- 10%, X7R, AEC-Q200 Grade 1, 1206; Manufacturer: Taiyo Yuden; AEC Qualified: Y; SizeZ_mm: 1.8; TaMax_C: 125°C; TaMin_C: -55°C; Cap_Case: 1206; Polarized: N; AEC Grade: 1; SizeY_mm: 1.6; Value: 10uF; SizeX_mm: 3.2; SizeAreaWB_mm2: 10.92; AEC Category: Q200; U/M: EA; SizeArea_mm2: 5.12
C11 = CMP-0095617-1: 0603 50 V 0.1 uF X7R ±10% Tolerance SMT Multilayer Ceramic Capacitor; Manufacturer: Murata; TempCo: 15%; SizeZ_mm: 0.9mm; AEC Qualified: No; ValueDisplayed: 0.1uF; Value: 100nF
C12 C13 = CMP-0128404-1: as C2 on sheet TIDA-011008_CoverSheet
C14 C15 = CMP-0045670-1: 220 pF ±5% 50V Ceramic Capacitor C0G, NP0 0603 (1608 Metric); Manufacturer: KEMET; AEC Qualified: No; SizeZ_mm: 0.87mm; TempCo: 30ppm/°C; Value: 220pF
C16 = CMP-0128435-1: Film Capacitor 3uF 10% 600V 32x11x20mm TH; Manufacturer: Jianghai; AEC Grade: NA; AEC Qualified: No; Cap_F: 3µF; SizeZ_mm: 20mm; Value: 3µF
C17 C18 = CMP-0009324-2: CAP, CERM, 0.1 uF, 1000 V, +/- 10%, X7R, 1812; Manufacturer: Kemet; TaMin_C: -55°C; Polarized: N; SizeAreaWB_mm2: 23.1; Value1: Unknown; U/M: EA; Value: 0.1uF; TaMax_C: 125°C; SizeZ_mm: 2.54; SizeX_mm: 4.5; SizeY_mm: 3.2; Cap_Case: 1812; Value2: 1000V; SizeArea_mm2: 14.4; Cap_F: 100nF; AEC Category: Q200
C21 = CMP-0086152-1: CAP, CERM, 1 µF, 25 V,+/- 10%, X5R, 0603; Manufacturer: Taiyo Yuden; SizeAreaWB_mm2: 4.68; SizeZ_mm: 1; U/M: EA; Green_REACh: Passed; Value: 1uF; AEC Qualified: N; TaMax_C: 85°C; Green_Lifecycle: Active; AEC Category: Q200; SizeArea_mm2: 1.28; TaMin_C: -55°C; SizeY_mm: 0.8; SizeX_mm: 1.6
C22 = CMP-0006752-5: CAP, CERM, 0.1 uF, 25 V, +/- 5%, X7R, 0603; Manufacturer: AVX; TaMin_C: -55°C; ESR_ohm: 0.05; Polarized: N; SizeAreaWB_mm2: 4.68; Value1: 0.05 ohm; U/M: EA; Value: 0.1uF; TaMax_C: 125°C; SizeZ_mm: 1; SizeX_mm: 1.6; SizeY_mm: 0.8; SizeArea_mm2: 1.28; AEC Category: Q200
C23 = CMP-0007197-4: CAP, CERM, 220 pF, 50 V, +/- 5%, C0G/NP0, 0603; Manufacturer: MuRata; TaMin_C: -55°C; Polarized: N; SizeAreaWB_mm2: 4.68; Value1: Unknown; U/M: EA; Value: 220pF; TaMax_C: 125°C; SizeZ_mm: 1; SizeX_mm: 1.6; SizeY_mm: 0.8; SizeArea_mm2: 1.28; AEC Category: Q200
C137 = CMP-0007378-5: CAP, CERM, 0.1 uF, 16 V, +/- 10%, X7R, 0603; Manufacturer: MuRata; TaMin_C: -55°C; Polarized: N; SizeAreaWB_mm2: 4.68; Value1: Unknown; U/M: EA; Value: 0.1uF; TaMax_C: 125°C; SizeZ_mm: 1; SizeX_mm: 1.6; SizeY_mm: 0.8; SizeArea_mm2: 1.28; AEC Category: Q200
D1 D15 = CMP-0128428-1: Silicon Carbide Diode 650 V 20A Surface Mount D2PAK; Manufacturer: WeEn Semiconductors; AEC Qualified: No; SizeZ_mm: 4.95mm; TJmax_C: 175°C; Vf_V: 650V; Cap_F: 780pF; Max Surge Forward Current: 120A; Peak Reverse Current: 1uA; Standoff Height: 0mm
FB1 = CMP-0037505-1: 600 Ohms @ 100 MHz 1 Power, Signal Line Ferrite Bead 0603 (1608 Metric) 1A 200mOhm; Manufacturer: Bourns; DCR_ohm: 0.2; SizeZ_mm: 1mm; AEC Qualified: No; Impedance At Frequency: 600Ω @ 100MHz; Test Frequency: 100MHz; Tolerance_%: 25%
J5 J6 = CMP-0078526-1: as J1 on sheet TIDA-011008_CoverSheet
L1 = CMP-0128165-1: 4.0mH CMC; Manufacturer: Huaihua Yaxin Electronics; DCR_ohm: 3.5m; Ind_H: 4mH; SizeZ_mm: 24mm; AEC Qualified: No; Test Frequency: 10kHz
R1 = CMP-0025743-4: RES, 1.0, 5%, 0.1 W, AEC-Q200 Grade 0, 0603; Manufacturer: Vishay-Dale; Power_W: 100mW; TempCo: 200 ppm/C; Value_Code: 1R00; Value: 1.0; EIA_Code: E24; Res_ohm: 1; SizeX_mm: 1.6; SizeY_mm: 0.8; Value2: 0.1W; SizeArea_mm2: 1.28; AEC Qualified: Y; VDC_V: 75V; AEC Category: Q200; AEC Grade: 0
R2 R4 R6 = CMP-0127835-1: 750 V 5 kA Varistor 1 Circuit Through Hole Disc 14mm; Manufacturer: TDK; SizeZ_mm: 18mm; AEC Qualified: No; Cap_F: 260pF; Clamping Voltage: 1240V; Varistor Voltage: 750V; Vc: 50A; VDC_V: 615V; Voltage Tolerance: 10%
R3 = CMP-0023169-5: RES, 51.0, 1%, 0.1 W, 0603; Manufacturer: Yageo; Power_W: 100mW; TempCo: 100 ppm/C; Value_Code: 51R0; Value: 51.0; Res_ohm: 51; SizeX_mm: 1.6; SizeY_mm: 0.8; SizeZ_mm: 1; Value2: 0.1W; SizeArea_mm2: 1.28; AEC Qualified: N; VDC_V: 75V; AEC Category: Q200; SizeAreaWB_mm2: 4.68
R5 = CMP-0023112-5: RES, 43.2 k, 1%, 0.1 W, 0603; Manufacturer: Yageo; Power_W: 100mW; TempCo: 100 ppm/C; Value_Code: 43k2; Value: 43.2k; EIA_Code: E96; SizeX_mm: 1.6; SizeY_mm: 0.8; SizeZ_mm: 1; Value2: 0.1W; SizeArea_mm2: 1.28; AEC Qualified: N; VDC_V: 75V; AEC Category: Q200; SizeAreaWB_mm2: 4.68
R7 = CMP-0120689-1: 2 mOhms ±1% 5W Chip Resistor 2512 (6432 Metric) Automotive AEC-Q200, Current Sense Metal Element; Manufacturer: Bourns; AEC Grade: Grade 0; AEC Qualified: Yes; SizeZ_mm: 1.09mm; TempCo: 75ppm/°C
R8 R11 = CMP-0025829-4: RES, 56, 5%, 0.1 W, AEC-Q200 Grade 0, 0603; Manufacturer: Vishay-Dale; Power_W: 100mW; TempCo: 200 ppm/C; Value_Code: 56R0; Value: 56; EIA_Code: E24; SizeX_mm: 1.6; SizeY_mm: 0.8; SizeZ_mm: 1; Value2: 0.1W; SizeArea_mm2: 1.28; AEC Qualified: Y; VDC_V: 75V; AEC Category: Q200; AEC Grade: 0
R9 = CMP-0126304-1: 10 kOhms ±1% 0.1W, 1/10W Chip Resistor 0603 (1608 Metric) Thick Film; Manufacturer: Vishay Semiconductor; AEC Qualified: No; Power_W: 100mW; SizeZ_mm: 0.55mm; TempCo: 100ppm/°C; VDC_V: 75V
R10 = CMP-0090742-1: 1 kOhms ±1% 0.1W, 1/10W Chip Resistor 0603 (1608 Metric) Thick Film; Manufacturer: Vishay; AEC Qualified: No; TempCo: 100ppm/°C; Power_W: 100mW; SizeZ_mm: 0.55mm; VDC_V: 75V
TP1-TP6 TP8-TP10 = CMP-0055138-2: Test Point, Miniature, Black, TH; Manufacturer: Keystone Electronics; ContactFinish: Silver; CNHeader: FALSE; Green_Lifecycle: Active; Green_REACh: Passed; CT: TRUE
U1 = CMP-0128366-1: Manufacturer: Texas Instruments; SizeZ_mm: 2.35mm; AEC Qualified: Unknown; AEC Grade: NA; Standoff Height: 0mm
U2 = CMP-0085242-1: Bidirectional, Precision Low- and High-Side Voltage Output, Current-Sense Amplifier, DRL0006A (SOT-5X3-6); Alternate PartNumber: INA185A2IDRLT; Alternate Manufacturer: Texas Instruments; SizeY_mm: 1.6; SizeAreaWB_mm2: 6.76; AEC Category: Q200; SizeArea_mm2: 2.56; CompType: IC; AEC Qualified: N; SizeZ_mm: 0.6

## Sheet TIDA-011008_ACDC_EMI Filter.SchDoc
size 431 x 279 mm; Date: Not shown in title block; ApprovedBy: Not shown in title block; CheckedBy: Not shown in title block; Author: Not shown in title block; CompanyName: Not shown in title block; Engineer: Not shown in title block; Organization: Not shown in title block; Address1: Not shown in title block; Address2: Not shown in title block; Address3: Not shown in title block; Address4: Not shown in title block; DocumentNumber: 1; Revision: Use project parameter SCH_Rev; SheetNumber: 6; SheetTotal: 10; PageSetup: Record=PageOptions¦CenterHorizontal=True¦CenterVertical=True¦PrintScale=1.00¦XCorrection=1.00¦YCorrection=1.00¦PrintKind=0¦BorderSize=5000000¦LeftOffset=0¦BottomOffset=0¦Orientation=2¦PaperLength=1000¦PaperWidth=1000¦Scale=100¦PaperSource=15¦PrintQuality=600¦MediaType=1¦DitherType=10¦PaperKind=Letter¦PrintScaleMode=1
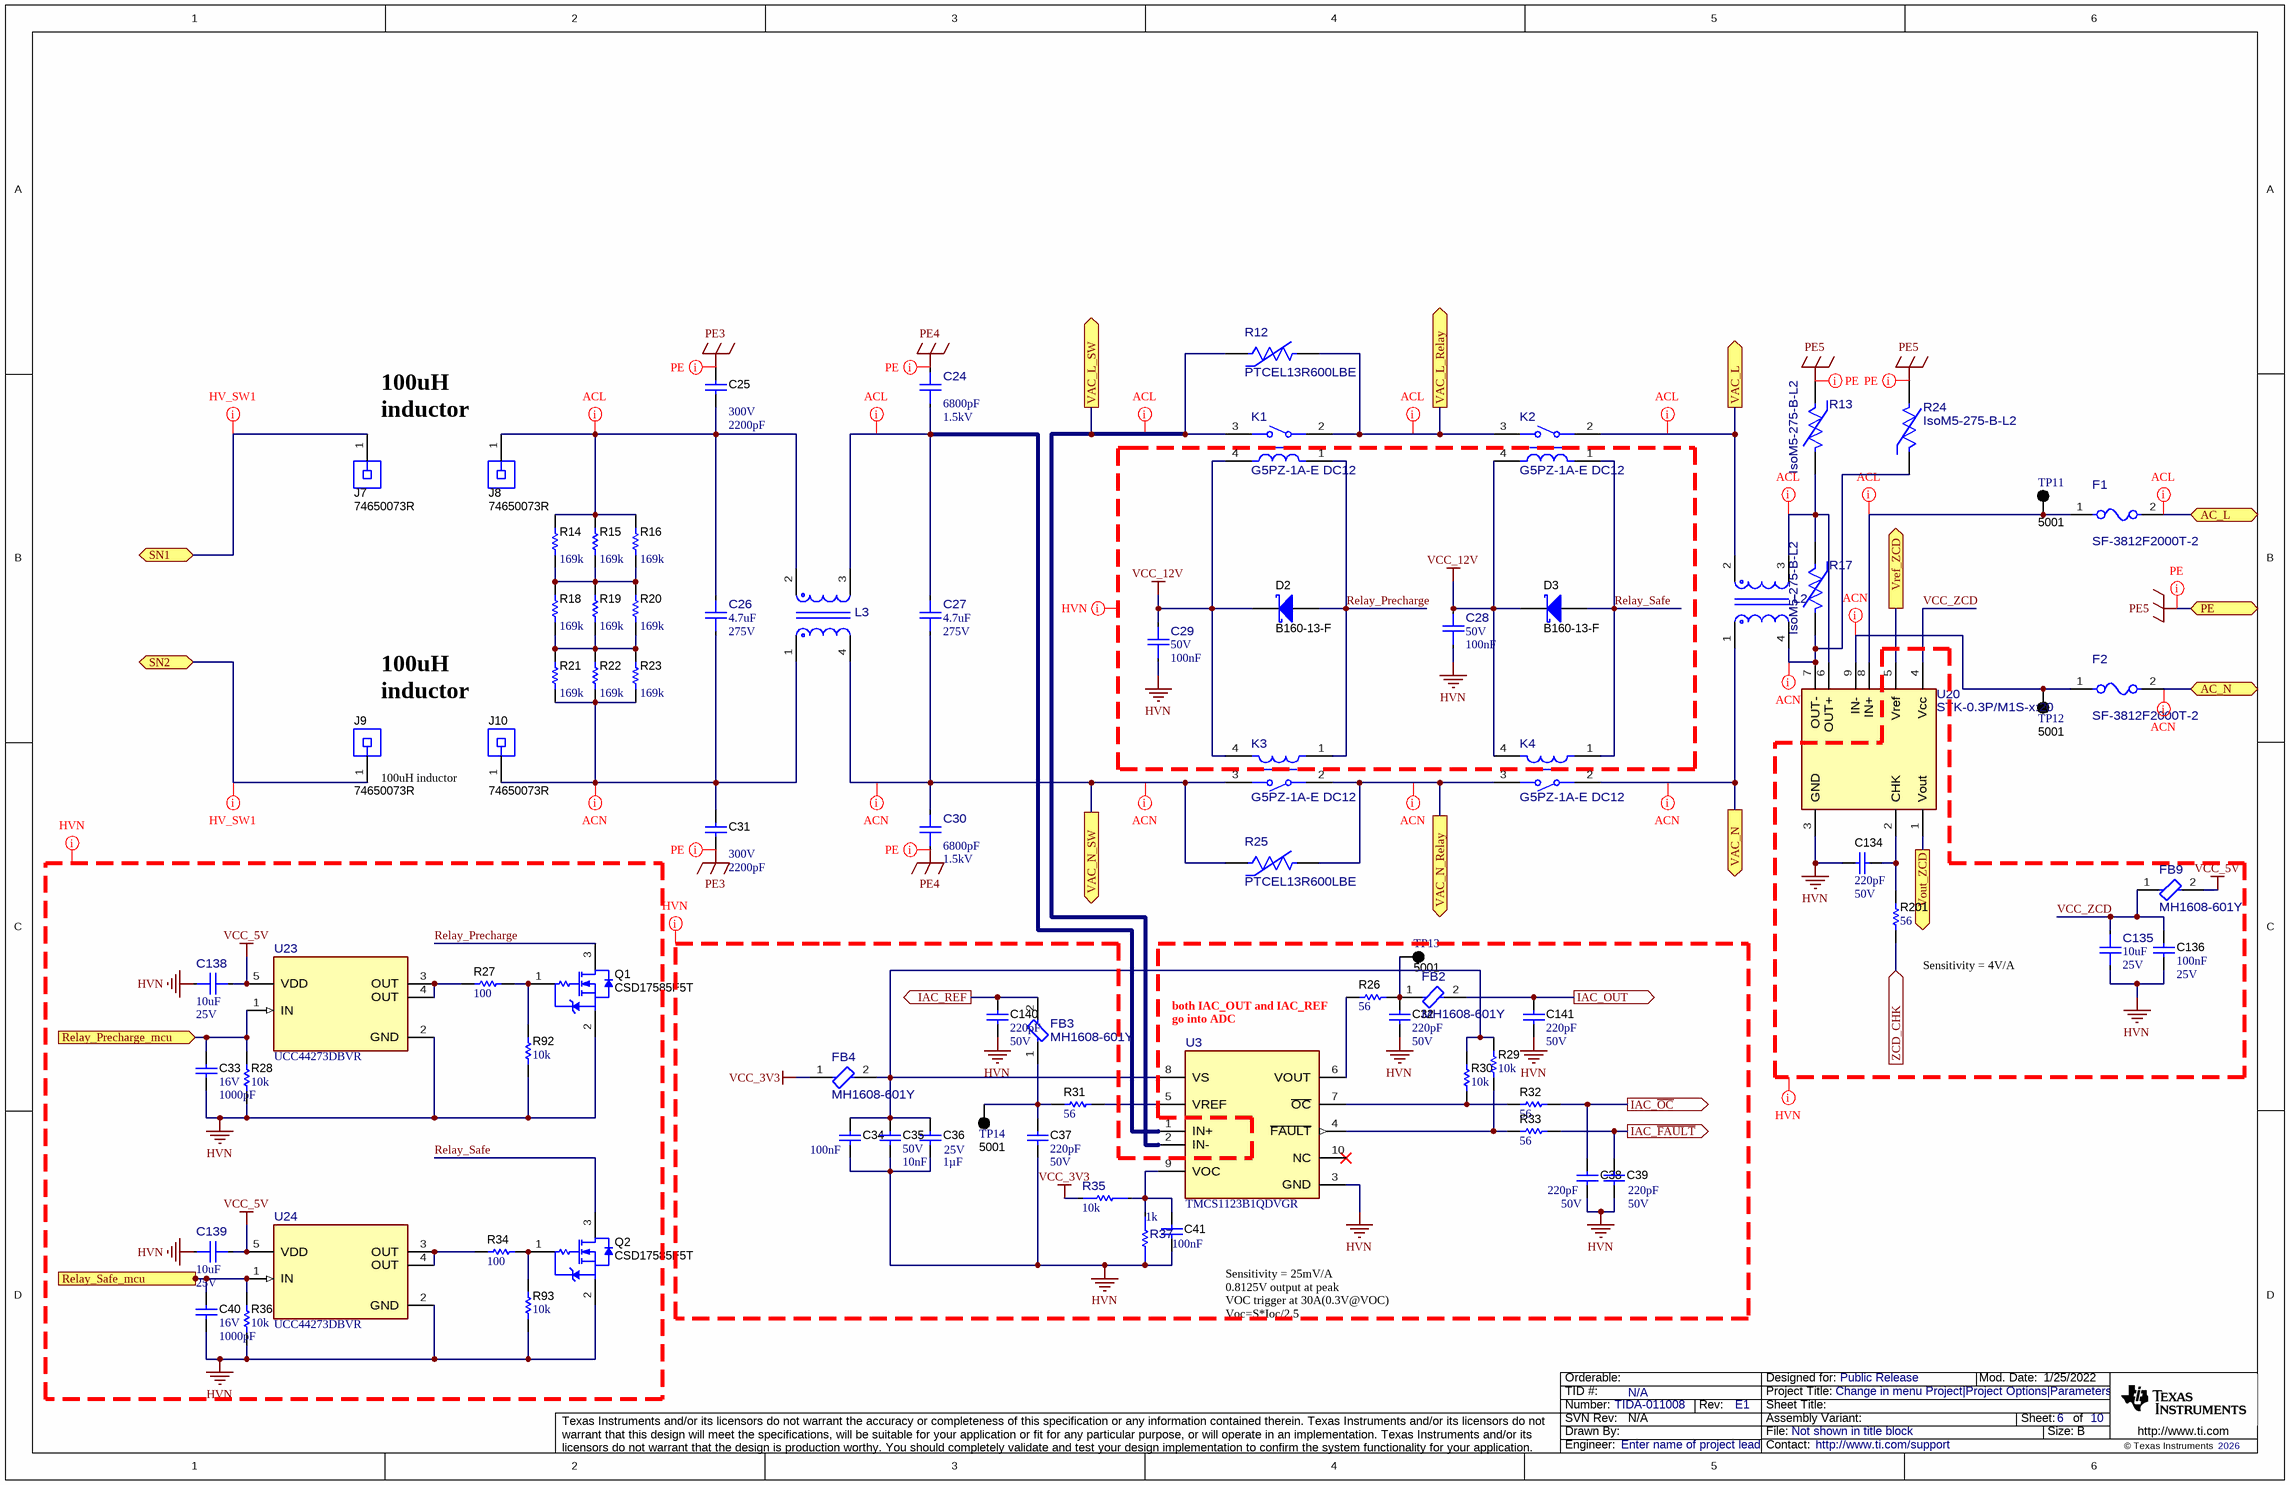
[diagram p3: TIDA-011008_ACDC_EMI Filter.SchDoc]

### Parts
C24  ValueDisplayed: 6800pF  VDC_V: 1.5kV  [FP-R413F168050T0K_RADIAL-MFG]  (hidden comment: R413F168050T0K)
C25  VDC_V: 300V  ValueDisplayed: 2200pF  [E_900x700x900]  (hidden comment: DE6E3KJ222MN3A)
C26  ValueDisplayed: 4.7uF  VDC_V: 275V  [FP-FCS3BAX475K050II90B_RADIAL-MFG]  (hidden comment: FCS3BAX475K050II90B)
C27  ValueDisplayed: 4.7uF  VDC_V: 275V  [FP-FCS3BAX475K050II90B_RADIAL-MFG]  (hidden comment: FCS3BAX475K050II90B)
C28  VDC_V: 50V  Cap_F: 100nF  [FP-GCM188R71H104KA57J_0603-MFG]  (hidden comment: GCM188R71H104KA57J)
C29  VDC_V: 50V  Cap_F: 100nF  [FP-GCM188R71H104KA57J_0603-MFG]  (hidden comment: GCM188R71H104KA57J)
C30  ValueDisplayed: 6800pF  VDC_V: 1.5kV  [FP-R413F168050T0K_RADIAL-MFG]  (hidden comment: R413F168050T0K)
C31  VDC_V: 300V  ValueDisplayed: 2200pF  [E_900x700x900]  (hidden comment: DE6E3KJ222MN3A)
C32  Cap_F: 220pF  VDC_V: 50V  [0603]  (hidden comment: GRM188R71H221KA01D)
C33  VDC_V: 16V  ValueDisplayed: 1000pF  [0402]  (hidden comment: GRM155R71C102KA01D)
C34  Cap_F: 100nF  [0603]  (hidden comment: GRM188R72A104KA35J)
C35  VDC_V: 50V  Cap_F: 10nF  [0603]  (hidden comment: 885012206089)
C36  VDC_V: 25V  ValueDisplayed: 1µF  [0603]  (hidden comment: TMK107BJ105KA-T)
C37  Cap_F: 220pF  VDC_V: 50V  [0603]  (hidden comment: GRM188R71H221KA01D)
C38  Cap_F: 220pF  VDC_V: 50V  [0603]  (hidden comment: GRM188R71H221KA01D)
C39  Cap_F: 220pF  VDC_V: 50V  [0603]  (hidden comment: GRM188R71H221KA01D)
C40  VDC_V: 16V  ValueDisplayed: 1000pF  [0402]  (hidden comment: GRM155R71C102KA01D)
C41  Cap_F: 100nF  [0603]  (hidden comment: GRM188R72A104KA35J)
C134  Cap_F: 220pF  VDC_V: 50V  [0603]  (hidden comment: GRM188R71H221KA01D)
C135  ValueDisplayed: 10uF  VDC_V: 25V  [FP-ZRB18AR61E106ME01L_0603-MFG]  (hidden comment: ZRB18AR61E106ME01L)
C136  Cap_F: 100nF  VDC_V: 25V  [0603]  (hidden comment: 06033C104JAT2A)
C138  ValueDisplayed: 10uF  VDC_V: 25V  [FP-ZRB18AR61E106ME01L_0603-MFG]  (hidden comment: ZRB18AR61E106ME01L)
C139  ValueDisplayed: 10uF  VDC_V: 25V  [FP-ZRB18AR61E106ME01L_0603-MFG]  (hidden comment: ZRB18AR61E106ME01L)
C140  Cap_F: 220pF  VDC_V: 50V  [0603]  (hidden comment: GRM188R71H221KA01D)
C141  Cap_F: 220pF  VDC_V: 50V  [0603]  (hidden comment: GRM188R71H221KA01D)
D2  B160-13-F  [SMA]
D3  B160-13-F  [SMA]
F1  SF-3812F2000T-2  [FP-SF-3812F2000T-2_3812-MFG]
F2  SF-3812F2000T-2  [FP-SF-3812F2000T-2_3812-MFG]
FB2  MH1608-601Y  [FP-MH1608-601Y_0603-MFG]
FB3  MH1608-601Y  [FP-MH1608-601Y_0603-MFG]
FB4  MH1608-601Y  [FP-MH1608-601Y_0603-MFG]
FB9  MH1608-601Y  [FP-MH1608-601Y_0603-MFG]
J7  74650073R  [Wurth_WP-THRBU]
J8  74650073R  [Wurth_WP-THRBU]
J9  74650073R  [Wurth_WP-THRBU]
J10  74650073R  [Wurth_WP-THRBU]
K1  G5PZ-1A-E DC12  [FP-G5PZ-1A-E DC12_PTH_RELAY_23MM8_10MM3-MFG]
K2  G5PZ-1A-E DC12  [FP-G5PZ-1A-E DC12_PTH_RELAY_23MM8_10MM3-MFG]
K3  G5PZ-1A-E DC12  [FP-G5PZ-1A-E DC12_PTH_RELAY_23MM8_10MM3-MFG]
K4  G5PZ-1A-E DC12  [FP-G5PZ-1A-E DC12_PTH_RELAY_23MM8_10MM3-MFG]
L2  YXA80182T-3  [FP-YXA80182T-3_pth4-MFG]  (value not drawn)
L3  YXA80182T-3  [FP-YXA80182T-3_pth4-MFG]  (value not drawn)
Q1  CSD17585F5T  [YJK0003A]
Q2  CSD17585F5T  [YJK0003A]
R12  PTCEL13R600LBE  [FP-PTCEL13R600LBE_RADIAL-MFG]
R13  IsoM5-275-B-L2  [FP-IsoM5-275-B-L2_RADIAL-MFG]
R14  ValueDisplayed: 169k  [1206]  (hidden comment: ERJ-8ENF1693V)
R15  ValueDisplayed: 169k  [1206]  (hidden comment: ERJ-8ENF1693V)
R16  ValueDisplayed: 169k  [1206]  (hidden comment: ERJ-8ENF1693V)
R17  IsoM5-275-B-L2  [FP-IsoM5-275-B-L2_RADIAL-MFG]
R18  ValueDisplayed: 169k  [1206]  (hidden comment: ERJ-8ENF1693V)
R19  ValueDisplayed: 169k  [1206]  (hidden comment: ERJ-8ENF1693V)
R20  ValueDisplayed: 169k  [1206]  (hidden comment: ERJ-8ENF1693V)
R21  ValueDisplayed: 169k  [1206]  (hidden comment: ERJ-8ENF1693V)
R22  ValueDisplayed: 169k  [1206]  (hidden comment: ERJ-8ENF1693V)
R23  ValueDisplayed: 169k  [1206]  (hidden comment: ERJ-8ENF1693V)
R24  IsoM5-275-B-L2  [FP-IsoM5-275-B-L2_RADIAL-MFG]
R25  PTCEL13R600LBE  [FP-PTCEL13R600LBE_RADIAL-MFG]
R26  ValueDisplayed: 56  [0603]  (hidden comment: CRCW060356R0JNEA)
R27  ValueDisplayed: 100  [0603]  (hidden comment: ESR03EZPJ101)
R28  ValueDisplayed: 10k  [0603]  (hidden comment: RC1608J103CS)
R29  ValueDisplayed: 10k  [0603]  (hidden comment: RC0603JR-0710KL)
R30  ValueDisplayed: 10k  [0603]  (hidden comment: RC0603JR-0710KL)
R31  ValueDisplayed: 56  [0603]  (hidden comment: CRCW060356R0JNEA)
R32  ValueDisplayed: 56  [0603]  (hidden comment: CRCW060356R0JNEA)
R33  ValueDisplayed: 56  [0603]  (hidden comment: CRCW060356R0JNEA)
R34  ValueDisplayed: 100  [0603]  (hidden comment: ESR03EZPJ101)
R35  value 10k  [FP-CRCW060310K0FKEAC_0603-MFG]  (hidden comment: CRCW060310K0FKEAC)
R36  ValueDisplayed: 10k  [0603]  (hidden comment: RC1608J103CS)
R37  value 1k  [FP-CRCW06031K00FKEAC_0603-MFG]  (hidden comment: CRCW06031K00FKEAC)
R92  ValueDisplayed: 10k  [0603]  (hidden comment: RC1608J103CS)
R93  ValueDisplayed: 10k  [0603]  (hidden comment: RC1608J103CS)
R201  ValueDisplayed: 56  [0603]  (hidden comment: CRCW060356R0JNEA)
TP11  5001  [Keystone5001]
TP12  5001  [Keystone5001]
TP13  5001  [Keystone5001]
TP14  5001  [Keystone5001]
U3  TMCS1123B1QDVGR  [DVG0010A-MFG]
U20  STK-0.3P/M1S-x:20  [FP-STK-0.3P%2FM1S-x_20_STK-x.xP%2FM1S-x-MFG]
U23  UCC44273DBVR  [DBV0005A-MFG]
U24  UCC44273DBVR  [DBV0005A-MFG]

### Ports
AC_L (bidir), AC_N (bidir), IAC_OUT (out), IAC_REF (out), IAC_~{FAULT} (out), IAC_~{OC} (out), PE (bidir), Relay_Precharge_mcu (in), Relay_Safe_mcu (in), SN1 (bidir), SN2 (bidir), VAC_L (out), VAC_L_Relay (out), VAC_L_SW (out), VAC_N (out), VAC_N_Relay (out), VAC_N_SW (out), Vout_ZCD (out), Vref_ZCD (out), ZCD_CHK (in)

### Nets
HVN: C28.1 C29.1 C32.1 C33.2 C34.2 C35.2 C36.2 C37.1 C38.1 C39.1 C40.2 C41.2 C134.2 C135.2 C136.1 C138.1 C139.1 C140.1 C141.1 Q1.2(S) Q2.2(S) R28.1 R36.1 R37.1 R92.1 R93.1 U3.3(GND) U20.3(GND) U23.2(GND) U24.2(GND)  [project net DC_Bus-]
PE3: C25.1 C31.2
PE4: C24.2 C30.1
PE5: R13.2 R24.1 ; port PE  [project net PE]
VCC_3V3: FB4.1 R35.2
VCC_5V: C138.2 C139.2 FB9.2 U23.5(VDD) U24.5(VDD)
VCC_12V: C28.2 C29.2 D2.1(K) D3.1(K) K1.4 K2.4 K3.4 K4.4
AC_L: F1.2 ; port AC_L
AC_N: F2.2 ; port AC_N
IAC_~{FAULT}: C39.2 R33.2 ; port IAC_~{FAULT}
IAC_~{OC}: C38.2 R32.2 ; port IAC_~{OC}
IAC_OUT: C141.2 FB2.2 ; port IAC_OUT
IAC_REF: C140.2 FB3.2 ; port IAC_REF
Relay_Precharge: D2.2(A) K1.1 K3.1 Q1.3(D)
Relay_Precharge_mcu: C33.1 R28.2 U23.1(IN) ; port Relay_Precharge_mcu
Relay_Safe: D3.2(A) K2.1 K4.1 Q2.3(D)
Relay_Safe_mcu: C40.1 R36.2 U24.1(IN) ; port Relay_Safe_mcu
SN1: J7.1 ; port SN1
SN2: J9.1 ; port SN2
VAC_L: K2.2 L2.2 ; port VAC_L
VAC_L_Relay: K1.2 K2.3 R12.2 ; port VAC_L_Relay
VAC_L_SW: K1.3 R12.1 U3.2(IN-) ; port VAC_L_SW
VAC_N: K4.2 L2.1 ; port VAC_N
VAC_N_Relay: K3.2 K4.3 R25.2 ; port VAC_N_Relay
VAC_N_SW: C27.1 C30.2 K3.3 L3.4 R25.1 ; port VAC_N_SW
VCC_ZCD: C135.1 C136.2 FB9.1 U20.4(Vcc)
Vout_ZCD: U20.1(Vout) ; port Vout_ZCD
Vref_ZCD: U20.5(Vref) ; port Vref_ZCD
ZCD_CHK: R201.1 ; port ZCD_CHK
NetC24_1: C24.1 C27.2 L3.3 U3.1(IN+)
NetC25_2: C25.2 C26.2 J8.1 L3.2 R14.2 R15.2 R16.2
NetC26_1: C26.1 C31.1 J10.1 L3.1 R21.1 R22.1 R23.1
NetC32_2: C32.2 FB2.1 R26.2 TP13.1
NetC34_1: C34.1 C35.1 C36.1 FB4.2 R29.2 R30.2 U3.8(VS)
NetC37_2: C37.2 FB3.1 R31.1 TP14.1
NetC41_1: C41.1 R35.1 R37.2 U3.9(VOC)
NetC134_1: C134.1 R201.2 U20.2(CHK)
NetF1_1: F1.1 TP11.1 U20.8(IN+)
NetF2_1: F2.1 TP12.1 U20.9(IN-)
NetL2_3: L2.3 R13.1 R17.2 U20.6(OUT+)
NetL2_4: L2.4 R17.1 R24.2 U20.7(OUT-)
NetQ1_1: Q1.1(G) R27.2 R92.2
NetQ2_1: Q2.1(G) R34.2 R93.2
NetR14_1: R14.1 R15.1 R16.1 R18.2 R19.2 R20.2
NetR18_1: R18.1 R19.1 R20.1 R21.2 R22.2 R23.2
NetR26_1: R26.1 U3.6(VOUT)
NetR27_1: R27.1 U23.3(OUT) U23.4(OUT)
NetR29_1: R29.1 R33.1 U3.4(~{FAULT})
NetR30_1: R30.1 R32.1 U3.7(~{OC})
NetR31_2: R31.2 U3.5(VREF)
NetR34_1: R34.1 U24.3(OUT) U24.4(OUT)

Not connected (* = marked no-connect by the designer): U3 10(NC)*

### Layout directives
net class HV_SW1: SN1, SN2
net class ACL: AC_L, NetC24_1, NetC25_2, NetF1_1, NetL2_3, VAC_L, VAC_L_Relay, VAC_L_SW
net class PE: PE, PE3, PE4
net class ACN: AC_N, NetC26_1, NetF2_1, NetL2_4, VAC_N, VAC_N_Relay, VAC_N_SW
net class HVN: HVN, Relay_Precharge, Relay_Safe, VCC_3V3, VCC_5V, VCC_12V, VCC_ZCD

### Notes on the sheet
- 100uH inductor
- (near R26) both IAC_OUT and IAC_REF go into ADC
- (near R201) Sensitivity = 4V/A
- Sensitivity = 25mV/A
  0.8125V output at peak
  VOC trigger at 30A(0.3V@VOC)
  Voc=S*Ioc/2.5

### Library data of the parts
C24 C30 = CMP-0042924-1: as C8 on sheet TIDA-011008_Boost
C25 C31 = CMP-0009613-2: CAP, CERM, 2200 pF, 300 V, +/- 20%, E, TH, 2- Leads, Body 9x7mm, Pin Spacing 7.5mm; Manufacturer: MuRata; TaMin_C: -40°C; Polarized: N; SizeAreaWB_mm2: 99; Value1: Unknown; U/M: EA; Value: 2200pF; TaMax_C: 125°C; SizeZ_mm: 12; SizeX_mm: 9; SizeY_mm: 7; Cap_Case: 9x7x9mm; SizeArea_mm2: 63; Cap_F: 2.2nF; AEC Category: Q200
C26 C27 = CMP-0128465-1: Film Capacitor 4.7uF 10% 305VAC 32x22x37mm TH; Manufacturer: Jianghai; AEC Qualified: No; Cap_F: 4.7µF; SizeZ_mm: 38mm; VAC: 305V; Value: 4.7µF
C28 C29 = CMP-0095617-1: as C11 on sheet TIDA-011008_Boost
C32 C37-C39 C134 C140 C141 = CMP-0007442-5: CAP, CERM, 220 pF, 50 V, +/- 10%, X7R, 0603; Manufacturer: MuRata; TaMin_C: -55°C; Polarized: N; SizeAreaWB_mm2: 4.68; Value1: Unknown; U/M: EA; Value: 220pF; TaMax_C: 125°C; SizeZ_mm: 1; SizeX_mm: 1.6; SizeY_mm: 0.8; SizeArea_mm2: 1.28; AEC Category: Q200
C33 C40 = CMP-0006638-2: CAP, CERM, 1000 pF, 16 V, +/- 10%, X7R, 0402; Manufacturer: MuRata; TaMin_C: -55°C; Polarized: N; SizeAreaWB_mm2: 3; Value1: Unknown; U/M: EA; Value: 1000pF; TaMax_C: 125°C; SizeZ_mm: 0.6; SizeX_mm: 1; SizeY_mm: 0.5; Cap_F: 1nF; AEC Category: Q200
C34 C41 = CMP-0007470-5: CAP, CERM, 0.1 uF, 100 V, +/- 10%, X7R, 0603; Manufacturer: MuRata; TaMin_C: -55°C; Polarized: N; SizeAreaWB_mm2: 4.68; Value1: Unknown; U/M: EA; Value: 0.1uF; TaMax_C: 125°C; SizeZ_mm: 1; SizeX_mm: 1.6; SizeY_mm: 0.8; Value2: 100V; SizeArea_mm2: 1.28; AEC Category: Q200
C35 = CMP-0750039-1: CAP, CERM, 0.01 µF, 50 V,+/- 10%, X7R, 0603; Manufacturer: Wurth Elektronik; Polarized: N; AEC Category: Q200; TaMax_C: 125°C; SizeAreaWB_mm2: 4.68; Value: 0.01uF; SizeArea_mm2: 1.28; SizeY_mm: 0.8; SizeZ_mm: 1; ValueDisplayed: 0.01µF; SizeX_mm: 1.6; U/M: EA; TaMin_C: -55°C
C36 = CMP-0086152-1: as C21 on sheet TIDA-011008_Boost
C135 C138 C139 = CMP-0094458-1: 10µF ±20% 25V Ceramic Capacitor X5R 0603 (1608 Metric); Manufacturer: Murata Electronics; SizeZ_mm: 1.2mm; AEC Qualified: No
C136 = CMP-0006752-5: as C22 on sheet TIDA-011008_Boost
D2 D3 = CMP-0028389-2: Diode, Schottky, 60 V, 1 A, SMA; Manufacturer: Diodes Inc.; Green_Lifecycle: Not Set; SizeAreaWB_mm2: 37.3428; Green_REACh: Incomplete; TJmax_C: 150°C; AEC Category: Q101; SizeZ_mm: 2.87; RJC_CperW: 20; Io_A: 1A; SizeArea_mm2: 16.3228; Vf_V: 700mV; Value2: 0.7V; SizeY_mm: 2.92; Vr_V: 60V; SizeX_mm: 5.59; Value: 60V
F1 F2 = CMP-0042962-1: 20 A 250 V AC 80 V DC Fuse Board Mount (Cartridge Style Excluded) Surface Mount 2-SMD, Square End Block; Manufacturer: Bourns; Interrupt_AC: 150A; Interrupt_DC: 300A; MeltingTyp: 356A2Sec; SizeZ_mm: 3.3mm; VAC_V: 250V; Fuse Speed: Fast; AEC Qualified: No; Fuse Current: 20A; Res_ohm: 0.003Ω
FB2-FB4 FB9 = CMP-0037505-1: as FB1 on sheet TIDA-011008_Boost
J7-J10 = CMP-0078526-1: as J1 on sheet TIDA-011008_CoverSheet
K1-K4 = CMP-0093993-1: General Purpose Relay SPST-NO (1 Form A) 12VDC Coil Through Hole; Manufacturer: Omron; TaMax_C: +70°C; Coil Current_A: 44.1mA; Standoff Height: 0.5mm; Switching Current: 20A; Coil Voltage_VDC: 12V; Coil Resistance: 272Ω; AEC Qualified: No; TaMin_C: -40°C; Coil Type: Non-Latching; SizeZ_mm: 25mm; Coil Power_W: 530mW
L2 L3 = CMP-0128165-1: as L1 on sheet TIDA-011008_Boost
Q1 Q2 = CMP-0067551-1: MOSFET, N-CH, 30 V, 5.9 A, YJK0003A (PICOSTAR-3); Alternate Manufacturer: None; Manufacturer: Texas Instruments; Rdson45_ohm: 0.033; QgTyp_nC: 1.9; SizeAreaWB_mm2: 4.3077; Vgs_V: 20V; Value1: 0.033 ohm; VdsMax_V: 30V; U/M: EA; Value: 30V; IdsMax_A: 5.9A; SizeZ_mm: 0.35; SizeX_mm: 1.49; SizeY_mm: 0.73; Value2: 1.9 nC; SizeArea_mm2: 1.0877; ChType: N; AEC Category: Q101
R12 R25 = CMP-0097004-1: PTCEL Series 500 V 60 Ohm ±30 % Radial Inrush Current Limiter PTC Thermistor; Manufacturer: Vishay Bccomponents; Value: 60Ω; SizeZ_mm: 17mm; AEC Qualified: Yes; Hold Current: 120mA; Tolerance_%: 30%; VDC_V: 500V; AEC Grade: Grade 2
R13 R17 R24 = CMP-0096768-1: 5 kA Varistor 1 Circuit Through Hole Disc 17mm; Manufacturer: Bourns; AEC Qualified: No; SizeZ_mm: 23mm; VDC_V: 350V; Vc: 100A; ValueDisplayed: 40pF; Clamping Voltage: 730V
R14-R16 R18-R23 = CMP-0017399-3: RES, 169 k, 1%, 0.25 W, AEC-Q200 Grade 0, 1206; Manufacturer: Panasonic; Power_W: 250mW; TempCo: 100 ppm/C; Value: 169k; EIA_Code: E96; SizeX_mm: 3.2; SizeY_mm: 1.6; SizeZ_mm: 1.35; Value2: 0.25W; SizeArea_mm2: 5.12; AEC Qualified: Y; VDC_V: 200V; AEC Category: Q200; AEC Grade: 0; SizeAreaWB_mm2: 10.92
R26 R31-R33 R201 = CMP-0025829-4: as R8 on sheet TIDA-011008_Boost
R27 R34 = CMP-0025882-3: RES, 100, 5%, 0.25 W, AEC-Q200 Grade 0, 0603; Manufacturer: Rohm; Power_W: 250mW; TempCo: 200 ppm/C; Value_Code: 100R; U/M: EA; Value: 100; EIA_Code: E24; SizeX_mm: 1.6; SizeY_mm: 0.8; SizeZ_mm: 1; Value2: 0.25W; SizeArea_mm2: 1.28; AEC Qualified: Y; VDC_V: 150V; AEC Grade: 0; AEC Category: Q200
R28 R36 R92 R93 = CMP-0025945-3: RES, 10 k, 5%, 0.1 W, 0603; Manufacturer: Samsung Electro-Mechanics; Power_W: 100mW; TempCo: 100 ppm/C; Value_Code: 10k0; U/M: EA; Value: 10k; EIA_Code: E24; SizeX_mm: 1.6; SizeY_mm: 0.8; SizeZ_mm: 1; Value2: 0.1W; SizeArea_mm2: 1.28; AEC Qualified: N; VDC_V: 31V; AEC Category: Q200
R29 R30 = CMP-0025886-5: RES, 10 k, 5%, 0.1 W, 0603; Manufacturer: Yageo; Power_W: 100mW; TempCo: 100 ppm/C; Value_Code: 10k0; Value: 10k; EIA_Code: E24; SizeX_mm: 1.6; SizeY_mm: 0.8; SizeZ_mm: 1; Value2: 0.1W; SizeArea_mm2: 1.28; AEC Qualified: N; VDC_V: 75V; AEC Category: Q200; SizeAreaWB_mm2: 4.68
R35 = CMP-0126304-1: as R9 on sheet TIDA-011008_Boost
R37 = CMP-0090742-1: as R10 on sheet TIDA-011008_Boost
TP11-TP14 = CMP-0055138-2: as TP1 on sheet TIDA-011008_Boost
U3 = CMP-0096051-1: Manufacturer: Texas Instruments; Standoff Height: 0.1mm; SizeZ_mm: 2.65mm; AEC Qualified: No
U20 = CMP-0128209-2: Current Sensor; Manufacturer: Sinomags; SizeZ_mm: 30.9mm; Accuracy: 2%; AEC Qualified: No; Coil Resistance: 0.36mΩ; Current Sensitivity: 4V/A; Max Sensing Current: 20A; Max Supply Voltage: 5.1V; Min Supply Voltage: 4.9V; Sensing Method: Hall Effect; Sensor Output: Analog Voltage; TaMax_C: +105°C; TaMin_C: -40°C
U23 U24 = CMP-0065552-1: Single-Channel High-Speed Low-Side Gate Driver with Negative Input Voltage Capability (with 4-A Peak Source and Sink); Manufacturer: Texas Instruments; SizeZ_mm: 1.45mm; AEC Qualified: No; Fall Time: 7ns; Max Supply Voltage: 18V; Min Supply Voltage: 4.5V; Number Of Drivers: 1; Propagation Delay: 13ns; Rise Time: 8ns; Standoff Height: 0mm; TJmax_C: +140°C

## Sheet TIDA-011008_Aux Power.SchDoc
size 558 x 431 mm; Date: Not shown in title block; ApprovedBy: Not shown in title block; CheckedBy: Not shown in title block; Author: Not shown in title block; CompanyName: Not shown in title block; Engineer: Not shown in title block; Organization: Not shown in title block; Address1: Not shown in title block; Address2: Not shown in title block; Address3: Not shown in title block; Address4: Not shown in title block; DocumentNumber: 1; Revision: Use project parameter SCH_Rev; SheetNumber: 8; SheetTotal: 10; PageSetup: Record=PageOptions¦CenterHorizontal=True¦CenterVertical=True¦PrintScale=1.00¦XCorrection=1.00¦YCorrection=1.00¦PrintKind=0¦BorderSize=5000000¦LeftOffset=0¦BottomOffset=0¦Orientation=2¦PaperLength=1000¦PaperWidth=1000¦Scale=100¦PaperSource=15¦PrintQuality=600¦MediaType=1¦DitherType=10¦PaperKind=Letter¦PrintScaleMode=1
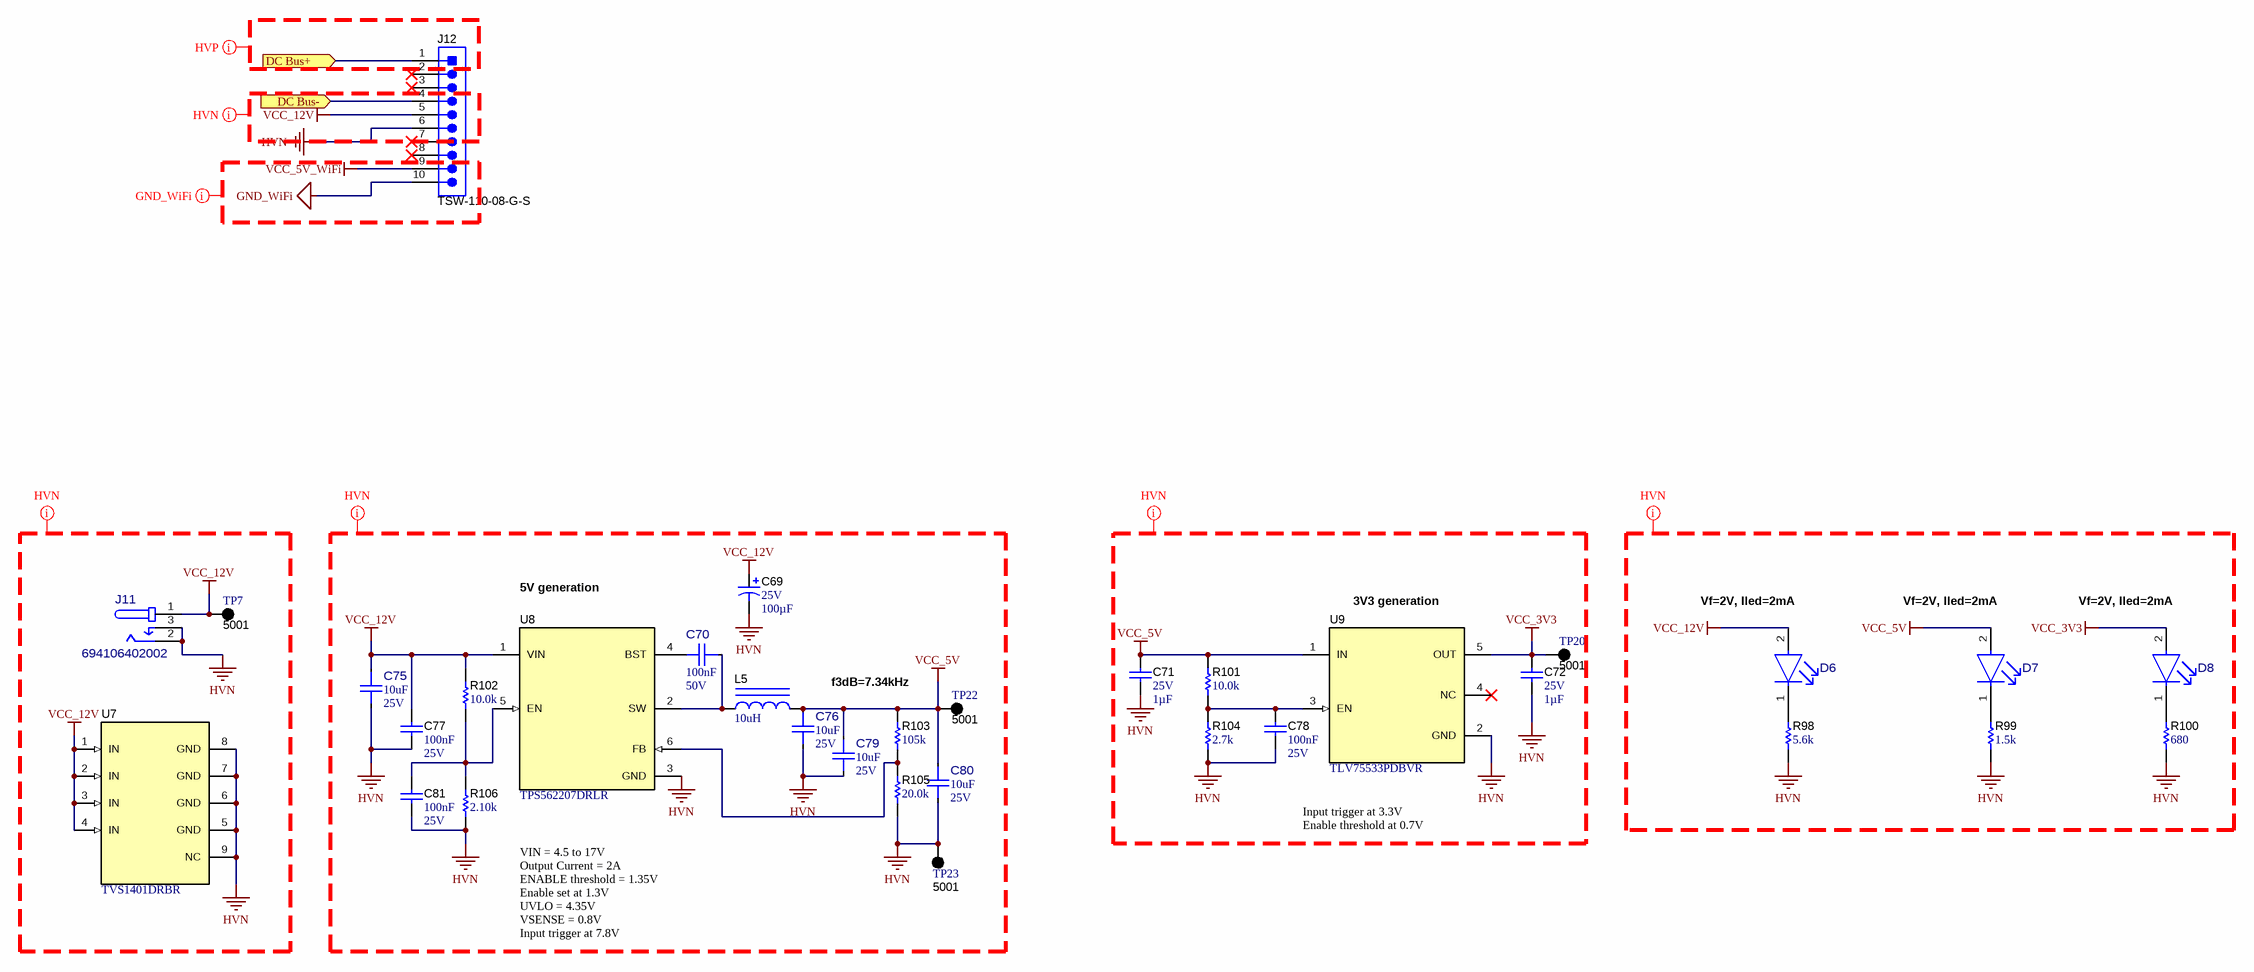
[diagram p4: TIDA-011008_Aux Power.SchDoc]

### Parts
C69  VDC_V: 25V  ValueDisplayed: 100µF  [UWT_630x770]  (hidden comment: UWT1E101MCL1GS)
C70  Cap_F: 100nF  VDC_V: 50V  [FP-GCE21BR71H104KA01L_0805-MFG]  (hidden comment: GCE21BR71H104KA01L)
C71  VDC_V: 25V  ValueDisplayed: 1µF  [0603]  (hidden comment: TMK107BJ105KA-T)
C72  VDC_V: 25V  ValueDisplayed: 1µF  [0603]  (hidden comment: TMK107BJ105KA-T)
C75  ValueDisplayed: 10uF  VDC_V: 25V  [FP-ZRB18AR61E106ME01L_0603-MFG]  (hidden comment: ZRB18AR61E106ME01L)
C76  ValueDisplayed: 10uF  VDC_V: 25V  [FP-ZRB18AR61E106ME01L_0603-MFG]  (hidden comment: ZRB18AR61E106ME01L)
C77  Cap_F: 100nF  VDC_V: 25V  [0603]  (hidden comment: 06033C104JAT2A)
C78  Cap_F: 100nF  VDC_V: 25V  [0603]  (hidden comment: 06033C104JAT2A)
C79  ValueDisplayed: 10uF  VDC_V: 25V  [FP-ZRB18AR61E106ME01L_0603-MFG]  (hidden comment: ZRB18AR61E106ME01L)
C80  ValueDisplayed: 10uF  VDC_V: 25V  [FP-ZRB18AR61E106ME01L_0603-MFG]  (hidden comment: ZRB18AR61E106ME01L)
C81  Cap_F: 100nF  VDC_V: 25V  [0603]  (hidden comment: 06033C104JAT2A)
D6  KG DELLS1.22-JGKH-24  [FP-KG DELLS1.22-JGKH-24_0603-MFG]  (value not drawn)
D7  KG DELLS1.22-JGKH-24  [FP-KG DELLS1.22-JGKH-24_0603-MFG]  (value not drawn)
D8  KG DELLS1.22-JGKH-24  [FP-KG DELLS1.22-JGKH-24_0603-MFG]  (value not drawn)
J11  694106402002  [FP-694106402002_CONN_PWR_10MM7_9MM0-MFG]
J12  TSW-110-08-G-S  [Samtec_TSW-110-08-x-S]
L5  ValueDisplayed: 10uH  [SRN3015]  (hidden comment: SRN3015-100M)
R98  ValueDisplayed: 5.6k  [0603]  (hidden comment: RC0603JR-075K6L)
R99  ValueDisplayed: 1.5k  [0603]  (hidden comment: ERJ-3GEYJ152V)
R100  ValueDisplayed: 680  [0603]  (hidden comment: RC0603JR-07680RL)
R101  ValueDisplayed: 10.0k  [0603]  (hidden comment: RCG060310K0FKEA)
R102  ValueDisplayed: 10.0k  [0603]  (hidden comment: RCG060310K0FKEA)
R103  ValueDisplayed: 105k  [0603]  (hidden comment: RC0603FR-07105KL)
R104  ValueDisplayed: 2.7k  [0603]  (hidden comment: CRCW06032K70JNEA)
R105  ValueDisplayed: 20.0k  [0603]  (hidden comment: ERJ-3EKF2002V)
R106  ValueDisplayed: 2.10k  [0603]  (hidden comment: CRCW06032K10FKEA)
TP7  5001  [Keystone5001]
TP20  5001  [Keystone5001]
TP22  5001  [Keystone5001]
TP23  5001  [Keystone5001]
U7  TVS1401DRBR  [DRB0008A]
U8  TPS562207DRLR  [DRL0006A]
U9  TLV75533PDBVR  [DBV0005A_N]

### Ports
DC Bus+ (in), DC Bus- (in)

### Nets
GND_WiFi: J12.10
HVN: C69.2(-) C71.1 C72.1 C75.2 C76.2 C77.1 C78.1 C79.2 C80.2 C81.1 J11.2 J11.3 J12.4 J12.6 R98.2 R99.1 R100.1 R104.1 R105.1 R106.1 TP23.1 U7.5(GND) U7.6(GND) U7.7(GND) U7.8(GND) U7.9(NC) U8.3(GND) U9.2(GND) ; port DC Bus-  [project net DC_Bus-]
VCC_3V3: C72.2 D8.2(ANODE) TP20.1 U9.5(OUT)
VCC_5V: C71.2 C76.1 C79.1 C80.1 D7.2(ANODE) L5.2 R101.2 R103.2 TP22.1 U9.1(IN)
VCC_5V_WiFi: J12.9
VCC_12V: C69.1(+) C75.1 C77.2 D6.2(ANODE) J11.1 J12.5 R102.2 TP7.1 U7.1(IN) U7.2(IN) U7.3(IN) U7.4(IN) U8.1(VIN)
DC_Bus+: J12.1 ; port DC Bus+
NetC70_1: C70.1 L5.1 U8.2(SW)
NetC70_2: C70.2 U8.4(BST)
NetC78_2: C78.2 R101.1 R104.2 U9.3(EN)
NetC81_2: C81.2 R102.1 R106.2 U8.5(EN)
NetD6_1: D6.1(CATHODE) R98.1
NetD7_1: D7.1(CATHODE) R99.2
NetD8_1: D8.1(CATHODE) R100.2
NetR103_1: R103.1 R105.2 U8.6(FB)

Not connected (* = marked no-connect by the designer): J12 2* 3* 7* 8*; U9 4(NC)*

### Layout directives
net class HVN: HVN, VCC_3V3, VCC_5V, VCC_12V
net class HVP: (no net found under the mark)
net class GND_WiFi: GND_WiFi, VCC_5V_WiFi

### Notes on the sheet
- 5V generation
- (near U9) 3V3 generation
- (near D6) Vf=2V, Iled=2mA
- (near D7) Vf=2V, Iled=2mA
- (near D8) Vf=2V, Iled=2mA
- f3dB=7.34kHz
- Input trigger at 3.3V
  Enable threshold at 0.7V
- VIN = 4.5 to 17V
  Output Current = 2A
  ENABLE threshold = 1.35V
  Enable set at 1.3V
  UVLO = 4.35V
  VSENSE = 0.8V
  Input trigger at 7.8V

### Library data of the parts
C69 = CMP-0081462-1: CAP, AL, 100 µF, 25 V, +/- 20%, SMD; Manufacturer: Nichicon; TaMin_C: -55°C; Polarized: Y; SizeAreaWB_mm2: 77.4; U/M: EA; Value: 100uF; TaMax_C: 105°C; SizeZ_mm: 8; SizeX_mm: 7; SizeY_mm: 6.6; Cap_Case: 6.3x7.7mm; SizeArea_mm2: 46.2; CompType: Capacitor; AEC Qualified: N; IRMS_A: 91mA; AEC Category: Q200
C70 = CMP-0088731-1: 0.1µF ±10% 50V Ceramic Capacitor X7R 0805 (2012 Metric); Manufacturer: Murata; SizeZ_mm: 1.45mm; TempCo: 15%; AEC Grade: Grade 1; AEC Qualified: Yes; ValueDisplayed: 0.1uF
C71 C72 = CMP-0086152-1: as C21 on sheet TIDA-011008_Boost
C75 C76 C79 C80 = CMP-0094458-1: as C135 on sheet TIDA-011008_ACDC_EMI Filter
C77 C78 C81 = CMP-0006752-5: as C22 on sheet TIDA-011008_Boost
D6-D8 = CMP-0093310-1: Standard LEDs - SMD Green TOPLED E 1608; Manufacturer: Osram Opto; AEC Grade: Grade 2; LambdaP: 572nm; SizeZ_mm: 0.7mm; LuminousFlux_PhiV: 0.016-0.0295lm; Luminous Intensity: 4.5-9.7mcd; LambdaD: 570nm; Tjmax_C: 125°C; Angle: 120°; Led Orientation: Top View; Forward Current: 2mA; Vf_V: 1.8V; AEC Qualified: Yes; Vr_V: 12V
J11 = CMP-0040211-1: Power Barrel Connector Jack 2.10mm ID (0.083"), 5.50mm OD (0.217") Through Hole; Manufacturer: Wurth Electronics; ContactFinish: Gold; Current_A: 3A; Voltage_V: 30V; AEC Qualified: No; Conn Gender: Female; Conn Orientation: Vertical; SizeZ_mm: 14.3mm
J12 = CMP-0055600-1: Header, 2.54mm, 10x1, Gold, TH; Manufacturer: Samtec; CNHeader: TRUE; Current_A: 6.3A; Shrouded: N; Gender: Male; Cert_CSA: Y; Voltage_V: 550V; Row_Count: 1; Pitch_mm: 2.54; CT: FALSE
L5 = CMP-0056744-1: Inductor, Drum Core, Ferrite, 10 uH, 0.88 A, 0.276 ohm, SMD; Manufacturer: Bourns; Isat: 0.88A @ 30% inductance drop; Irms: 1A @ 40C rise; Green_Lifecycle: Active; SizeAreaWB_mm2: 16; DCR_ohm: 2.76d; Green_REACh: Passed; Value: 10uH; Imax_A: 8.8dA; SizeZ_mm: 1.5; SizeX_mm: 3; Value2: 0.88A; SizeArea_mm2: 9; Ind_H: 10µH; AEC Category: Q200
R98 = CMP-0025933-5: RES, 5.6 k, 5%, 0.1 W, 0603; Manufacturer: Yageo; Power_W: 100mW; TempCo: 100 ppm/C; Value_Code: 5k60; Value: 5.6k; EIA_Code: E24; SizeX_mm: 1.6; SizeY_mm: 0.8; SizeZ_mm: 1; Value2: 0.1W; SizeArea_mm2: 1.28; AEC Qualified: N; VDC_V: 75V; AEC Category: Q200; SizeAreaWB_mm2: 4.68
R99 = CMP-0025877-3: RES, 1.5 k, 5%, 0.1 W, AEC-Q200 Grade 0, 0603; Manufacturer: Panasonic; Power_W: 100mW; TempCo: 200 ppm/C; Value_Code: 1k50; U/M: EA; Value: 1.5k; EIA_Code: E24; SizeX_mm: 1.6; SizeY_mm: 0.8; SizeZ_mm: 1; Value2: 0.1W; SizeArea_mm2: 1.28; AEC Qualified: Y; VDC_V: 75V; AEC Grade: 0; AEC Category: Q200
R100 = CMP-0025936-5: RES, 680, 5%, 0.1 W, 0603; Manufacturer: Yageo; Power_W: 100mW; TempCo: 100 ppm/C; Value_Code: 680R; Value: 680; EIA_Code: E24; SizeX_mm: 1.6; SizeY_mm: 0.8; SizeZ_mm: 1; Value2: 0.1W; SizeArea_mm2: 1.28; AEC Qualified: N; VDC_V: 75V; AEC Category: Q200; SizeAreaWB_mm2: 4.68
R101 R102 = CMP-0023337-3: RES, 10.0 k, 1%, 0.1 W, 0603; Manufacturer: Vishay Draloric; Power_W: 100mW; TempCo: 100 ppm/C; Value_Code: 10k0; U/M: EA; Value: 10.0k; EIA_Code: E96; Res_ohm: 10k; SizeX_mm: 1.6; SizeY_mm: 0.8; SizeZ_mm: 1; Value2: 0.1W; SizeArea_mm2: 1.28; AEC Qualified: N; VDC_V: 75V; AEC Category: Q200
R103 = CMP-0022739-4: RES, 105 k, 1%, 0.1 W, 0603; Manufacturer: Yageo; Power_W: 100mW; TempCo: 100 ppm/C; Value: 105k; EIA_Code: E96; SizeX_mm: 1.6; SizeY_mm: 0.8; SizeZ_mm: 1; Value2: 0.1W; SizeArea_mm2: 1.28; AEC Qualified: N; VDC_V: 75V; AEC Category: Q200; SizeAreaWB_mm2: 4.68
R104 = CMP-0025771-4: RES, 2.7 k, 5%, 0.1 W, AEC-Q200 Grade 0, 0603; Manufacturer: Vishay-Dale; Power_W: 100mW; TempCo: 200 ppm/C; Value_Code: 2k70; Value: 2.7k; EIA_Code: E24; SizeX_mm: 1.6; SizeY_mm: 0.8; SizeZ_mm: 1; Value2: 0.1W; SizeArea_mm2: 1.28; AEC Qualified: Y; VDC_V: 75V; AEC Category: Q200; AEC Grade: 0
R105 = CMP-0022691-3: RES, 20.0 k, 1%, 0.1 W, AEC-Q200 Grade 0, 0603; Manufacturer: Panasonic; Power_W: 100mW; TempCo: 100 ppm/C; Value_Code: 20k0; U/M: EA; Value: 20.0k; Res_ohm: 20k; SizeX_mm: 1.6; SizeY_mm: 0.8; SizeZ_mm: 1; Value2: 0.1W; SizeArea_mm2: 1.28; AEC Qualified: Y; VDC_V: 75V; AEC Grade: 0; AEC Category: Q200; EIA_Code: E96
R106 = CMP-0022270-4: RES, 2.10 k, 1%, 0.1 W, AEC-Q200 Grade 0, 0603; Manufacturer: Vishay-Dale; Power_W: 100mW; TempCo: 100 ppm/C; Value_Code: 2k10; Value: 2.10k; EIA_Code: E96; Res_ohm: 2.1k; SizeX_mm: 1.6; SizeY_mm: 0.8; SizeZ_mm: 1; Value2: 0.1W; SizeArea_mm2: 1.28; AEC Qualified: Y; VDC_V: 75V; AEC Category: Q200; AEC Grade: 0
TP7 TP20 TP22 TP23 = CMP-0055138-2: as TP1 on sheet TIDA-011008_Boost
U7 = CMP-0083940-3: 14 V Bidirectional Flat-Clamp Surge Protection Device, DRB0008A (VSON-8); Alternate PartNumber: TVS1401DRBT; Alternate Manufacturer: Texas Instruments; CompType: IC; SizeAreaWB_mm2: 16.0; SizeZ_mm: 1.0; SizeY_mm: 3.0; AEC Category: Q200; SizeArea_mm2: 9.0; AEC Qualified: N
U8 = CMP-0860516-1: 4.5-V to 17-V Input, 2-A Synchronous Buck Converter, DRL0006A (SOT-5X3-6); Alternate Manufacturer: Texas Instruments; SizeZ_mm: 0.6; AEC Category: Q200; SizeAreaWB_mm2: 6.76; SizeX_mm: 1.6; SizeArea_mm2: 2.56; AEC Qualified: N; CompType: IC
U9 = CMP-0074640-3: 500-mA, Low IQ, Small Size, Low Dropout Regulator, DBV0005A (SOT-23-5); Manufacturer: Texas Instruments; SizeX_mm: 2.8; SizeY_mm: 2.9; CompType: IC; SizeZ_mm: 1.45; SizeArea_mm2: 8.12; SizeAreaWB_mm2: 14.82; AEC Category: Q200; AEC Qualified: N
